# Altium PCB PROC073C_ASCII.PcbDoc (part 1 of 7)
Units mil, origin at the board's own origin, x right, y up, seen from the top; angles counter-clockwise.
Board outline 2165.35 x 2695.12 mil, 8 copper layers (Top Layer, L2_GND, L3_SIGNAL 1, L4_SIGNAL 2, L5_SIGNAL 3, L6_SIGNAL 4, L7_GND, Bottom Layer), stack 55.9 mil thick; 393 components, 319 nets, 1311 pads, 1643 vias.
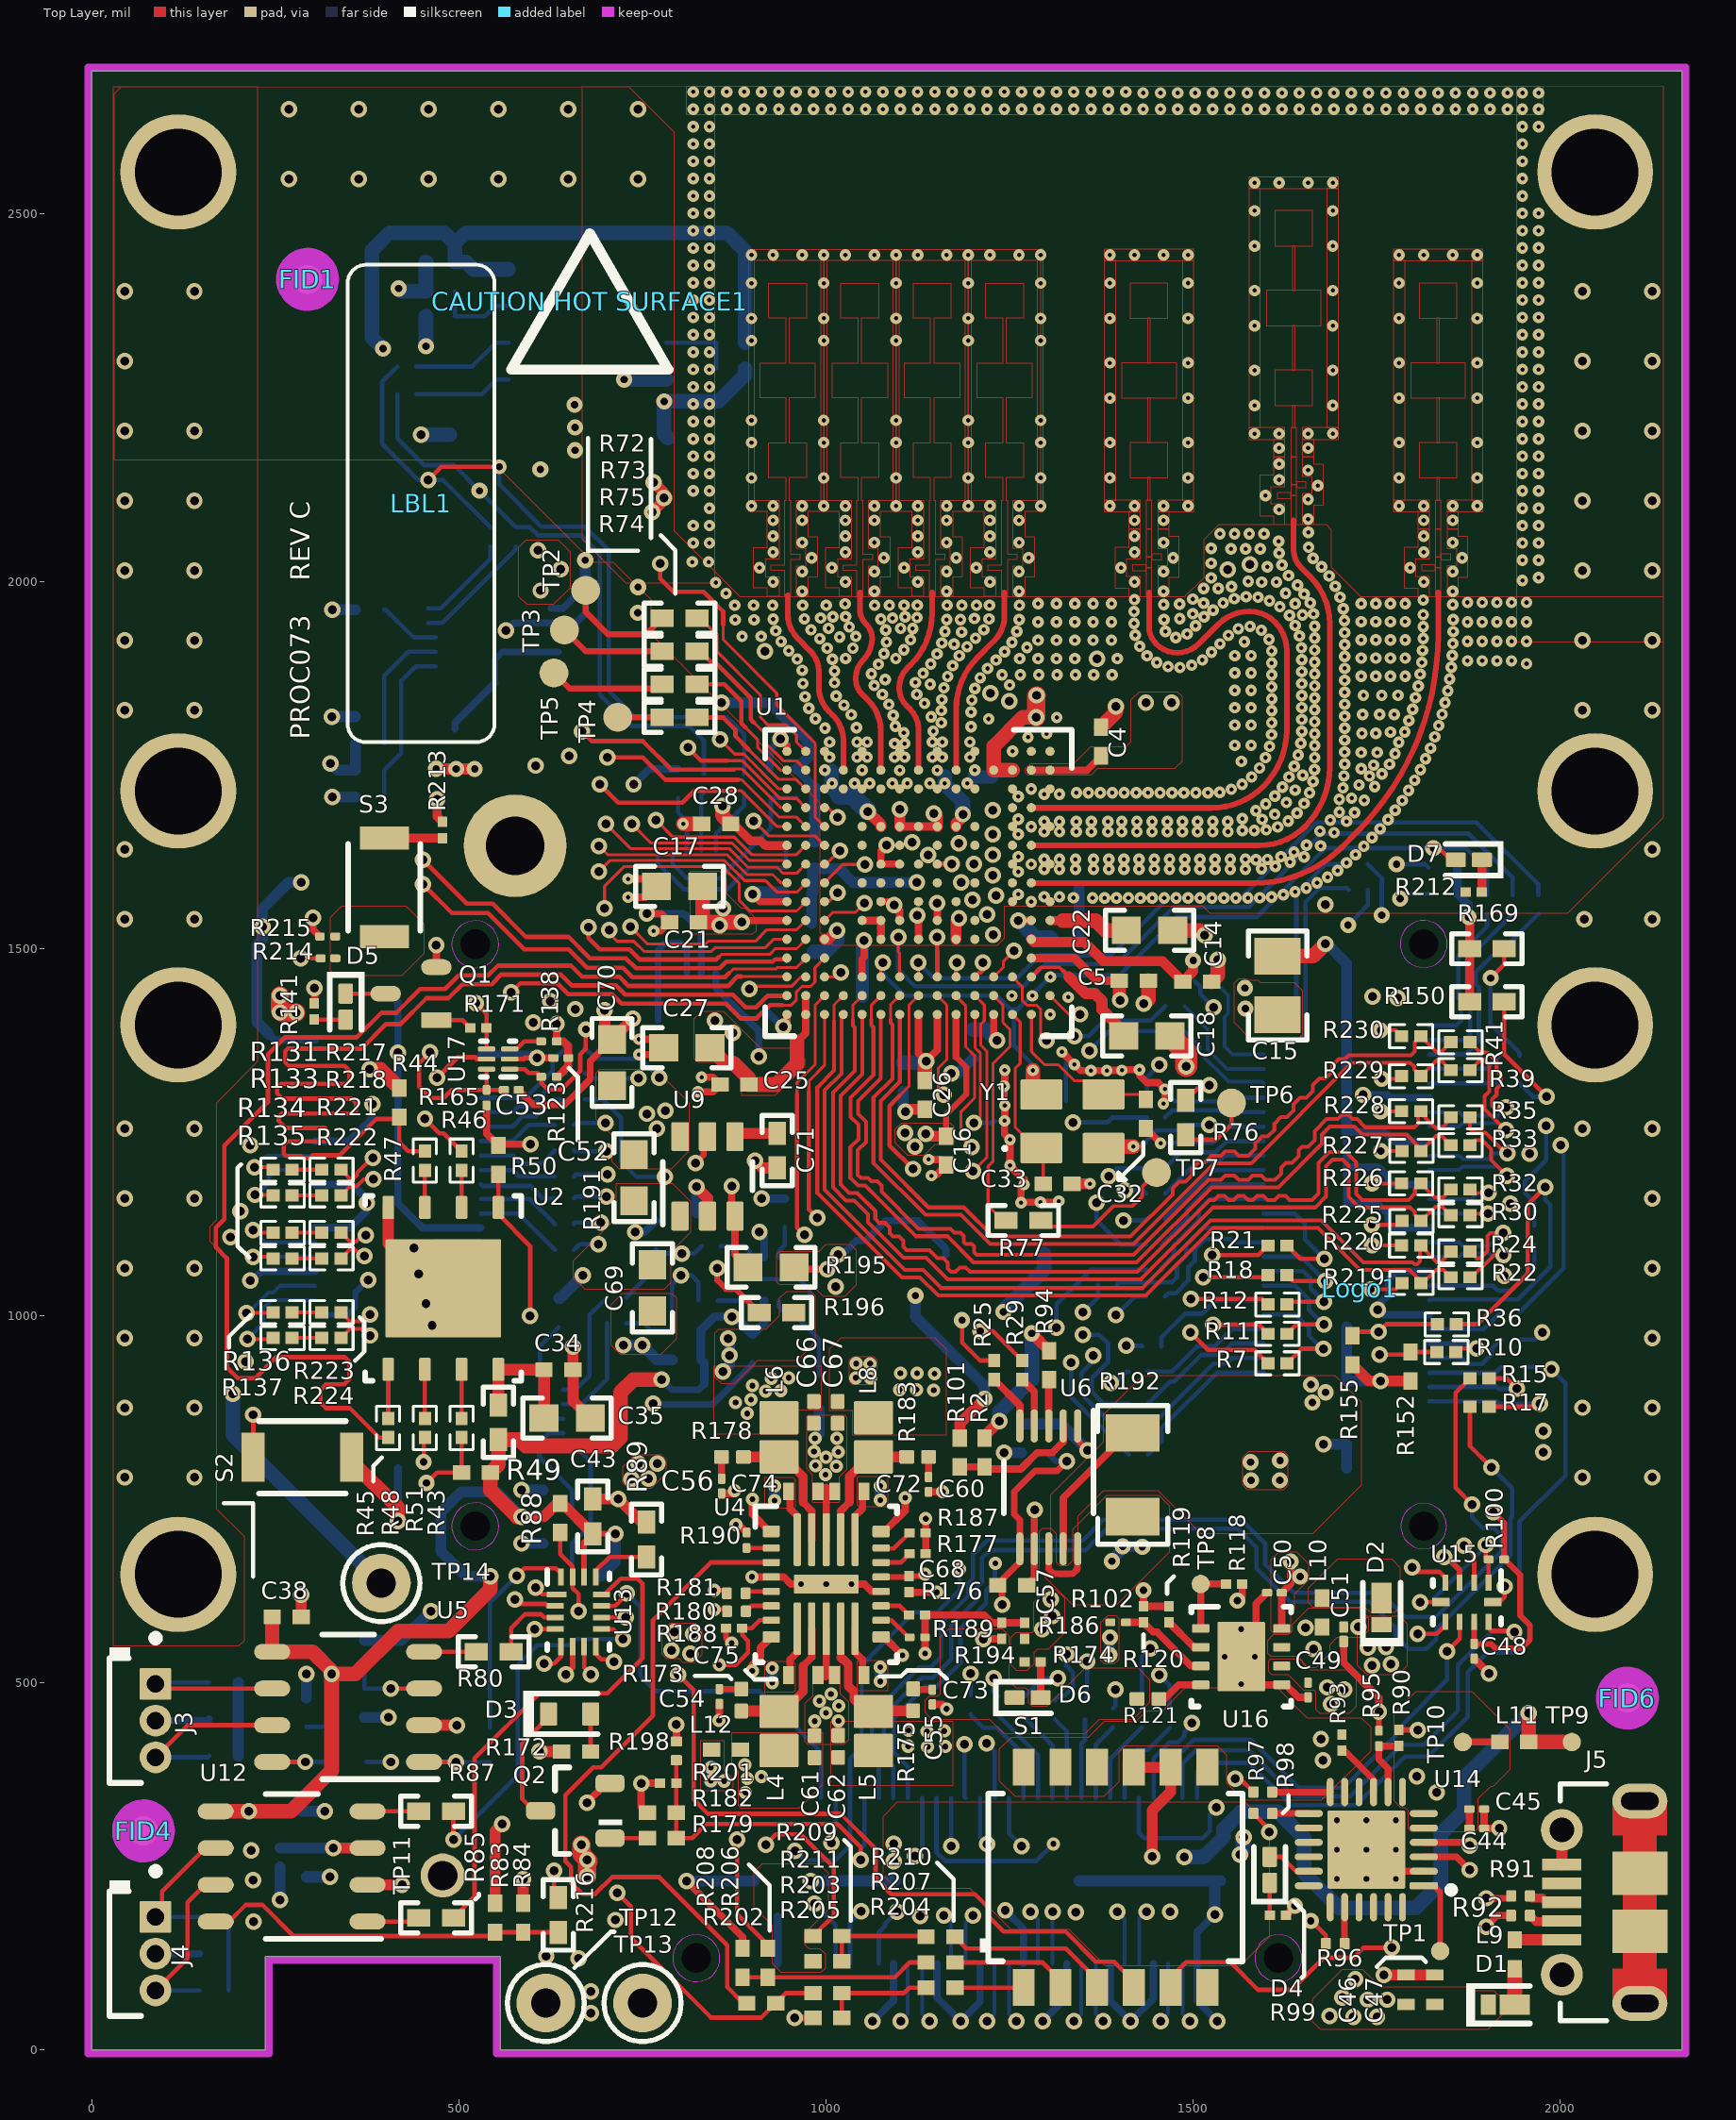
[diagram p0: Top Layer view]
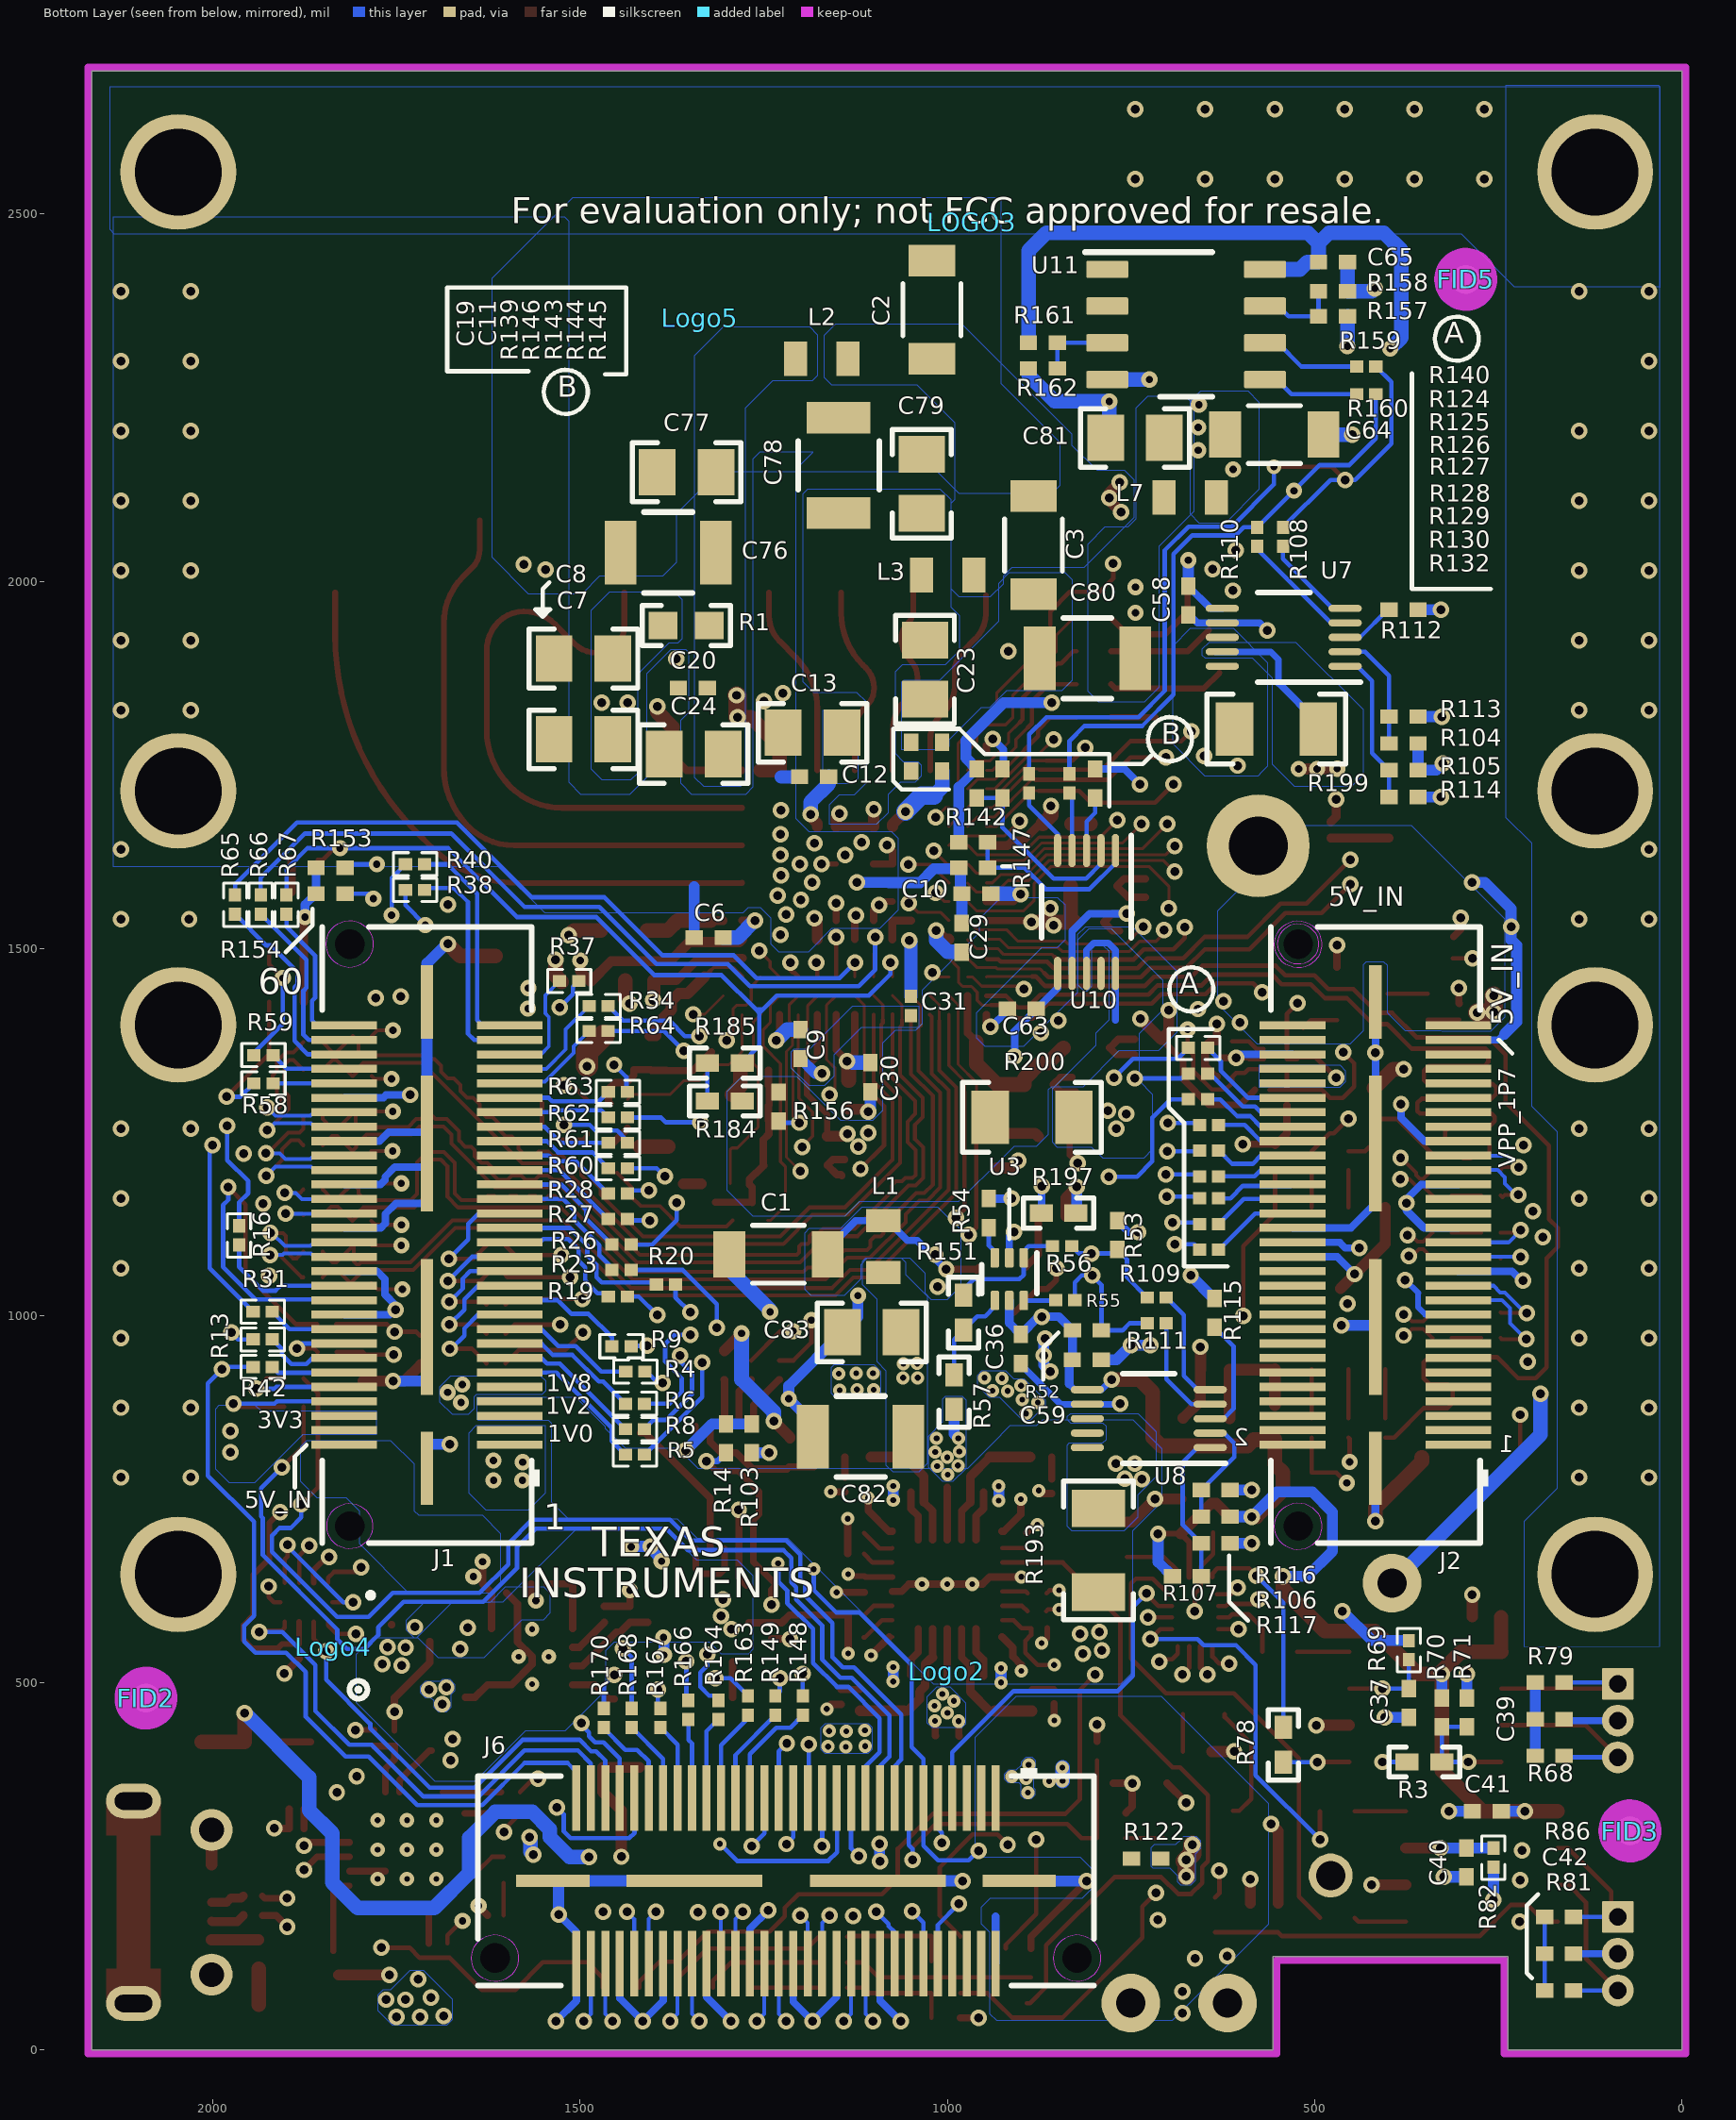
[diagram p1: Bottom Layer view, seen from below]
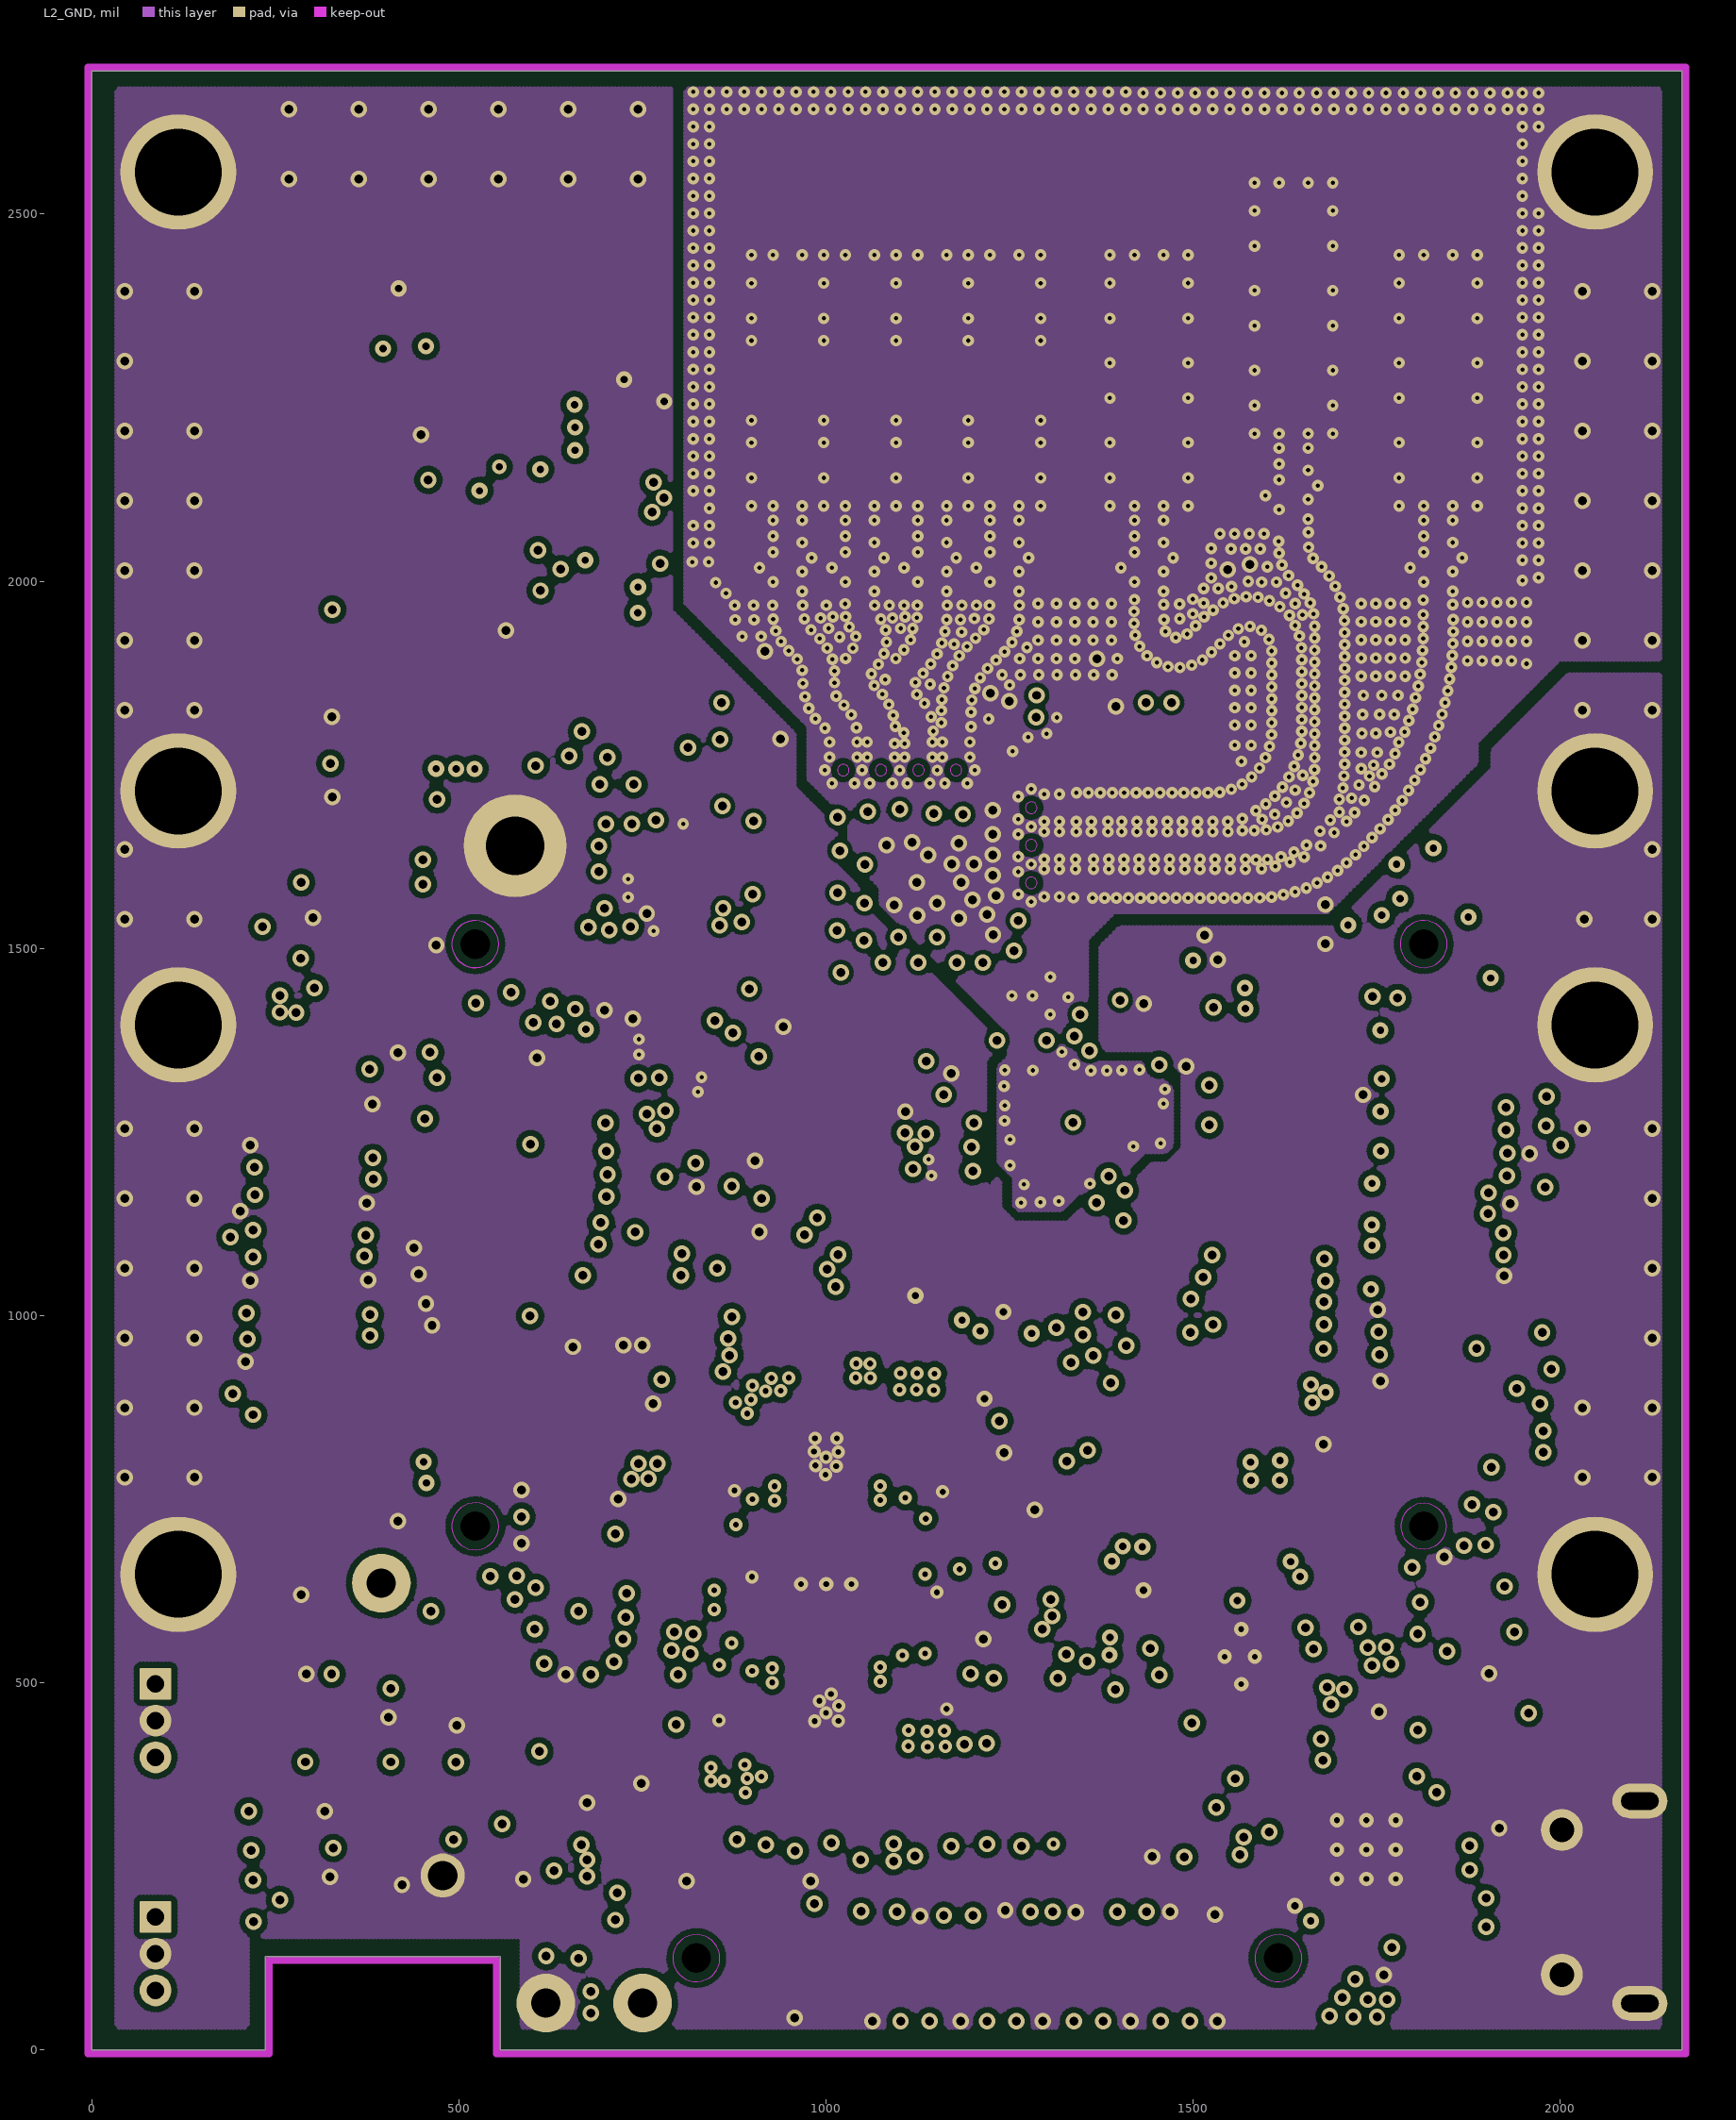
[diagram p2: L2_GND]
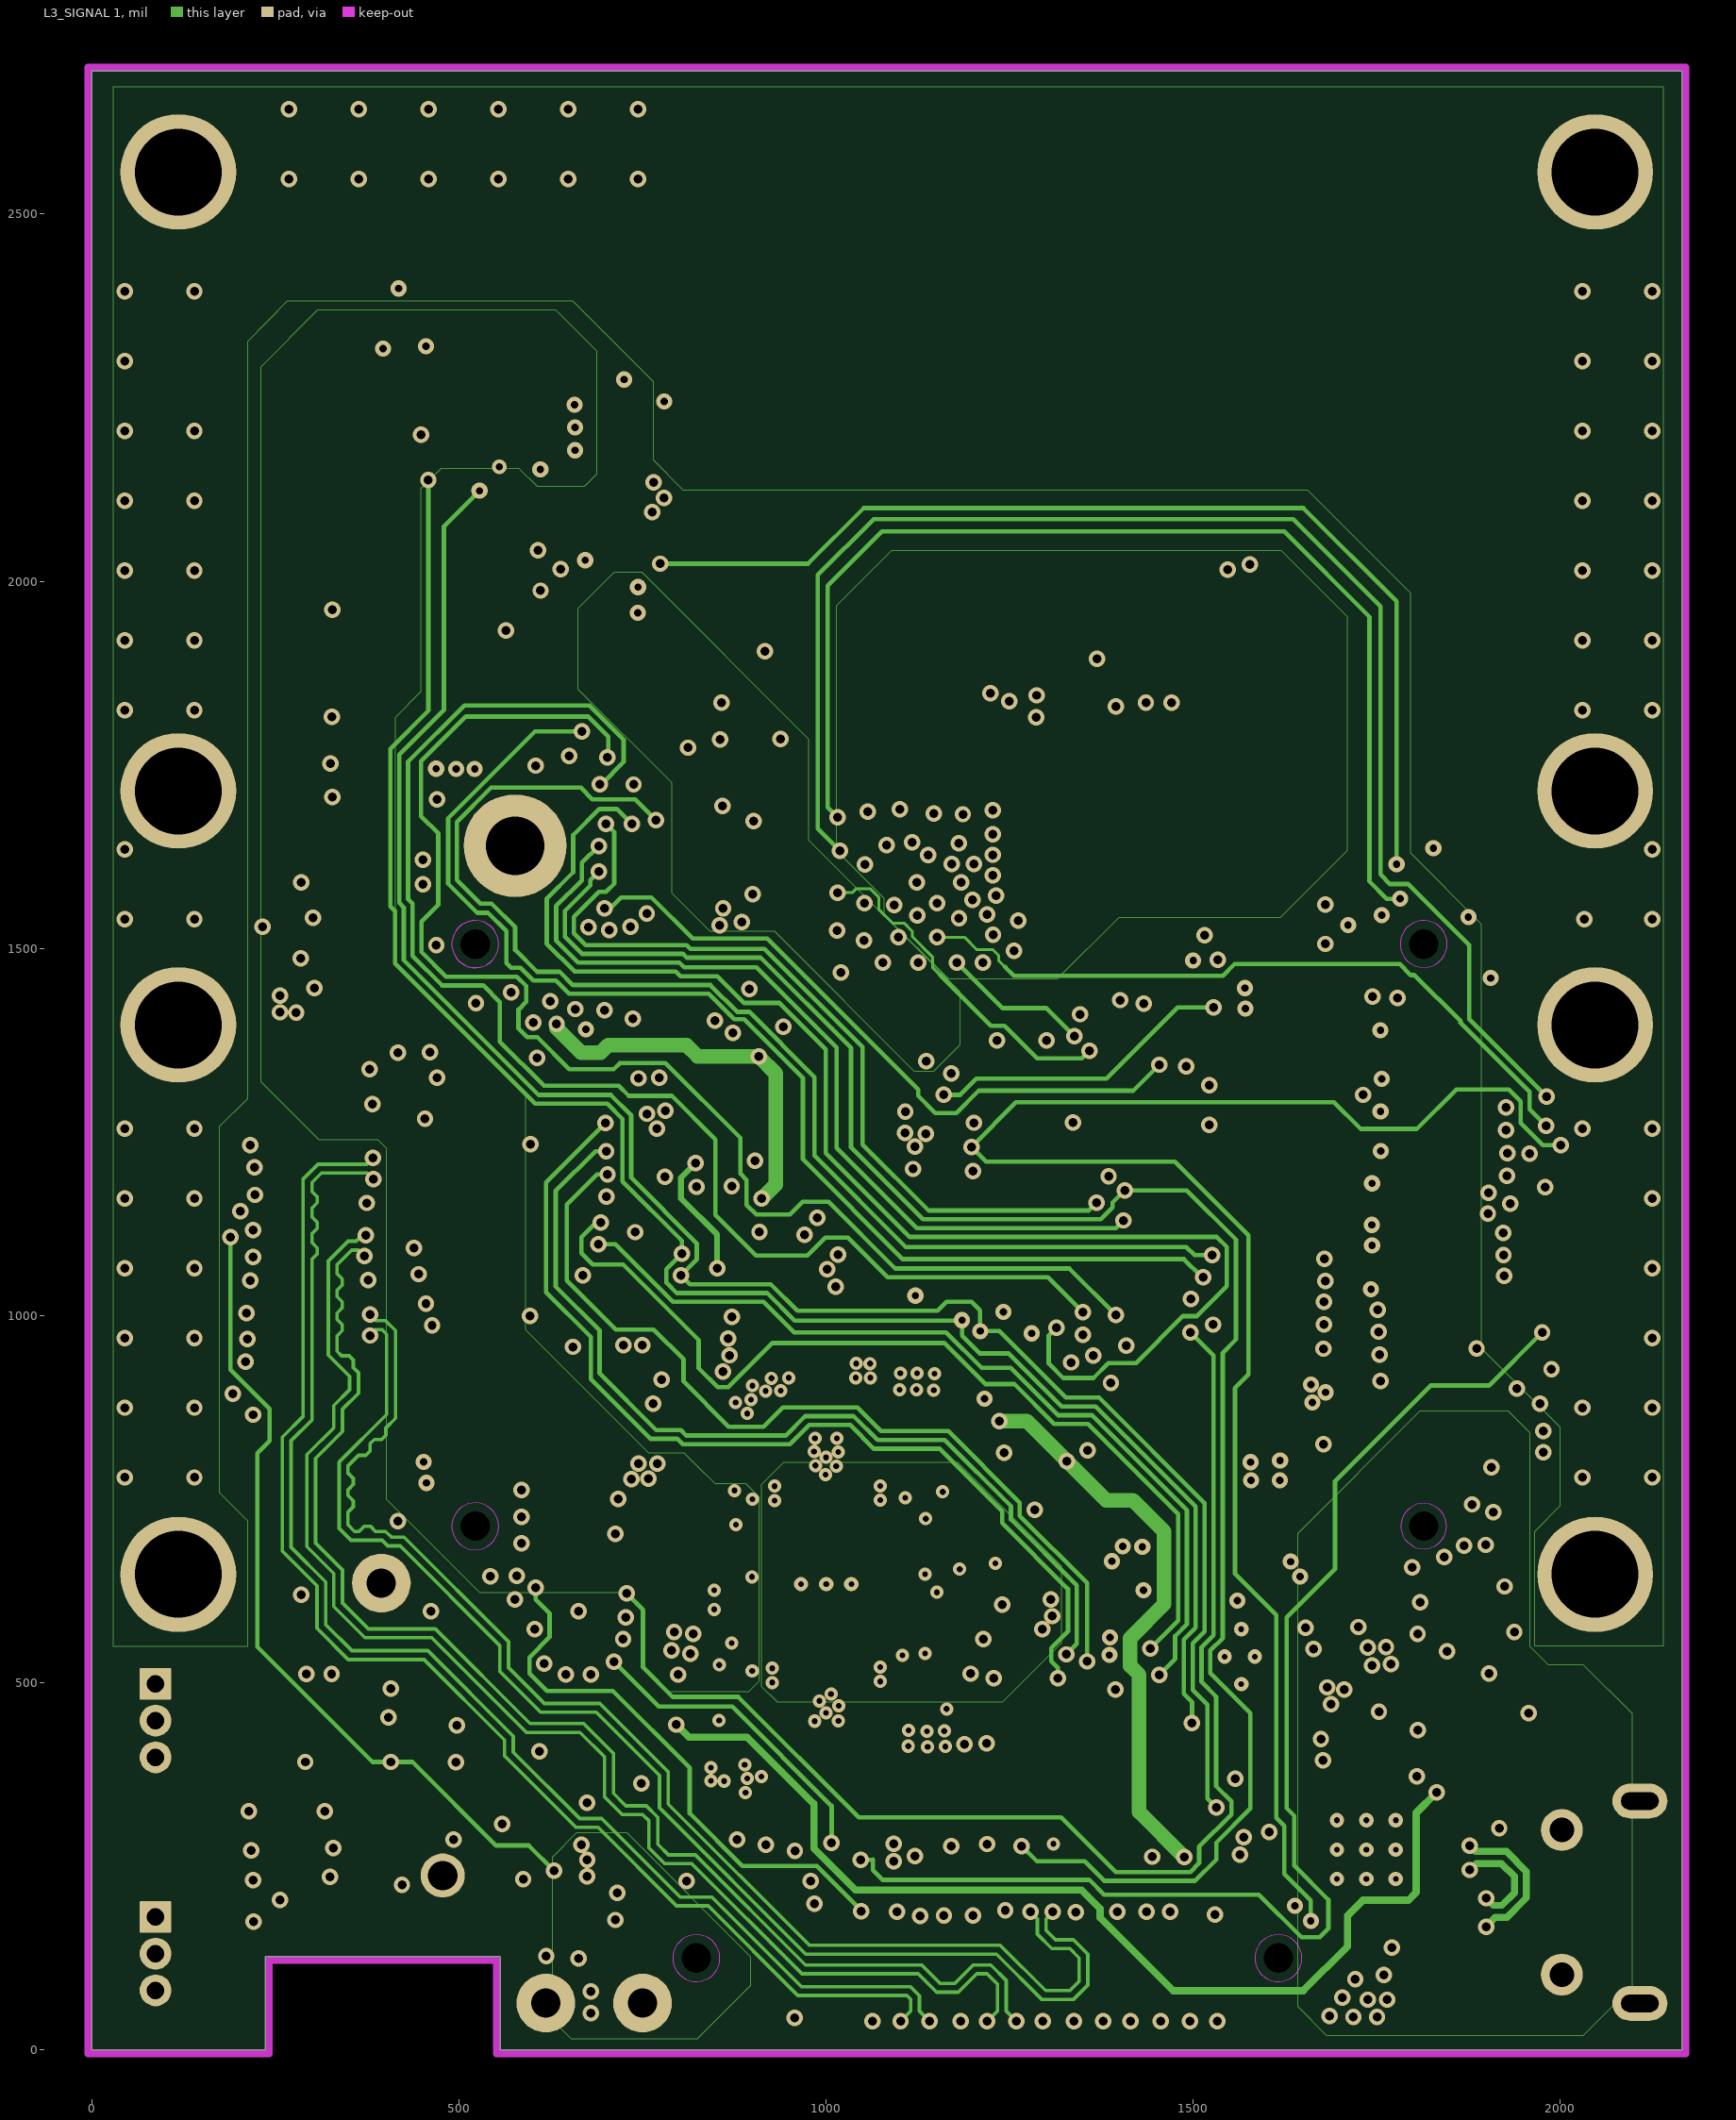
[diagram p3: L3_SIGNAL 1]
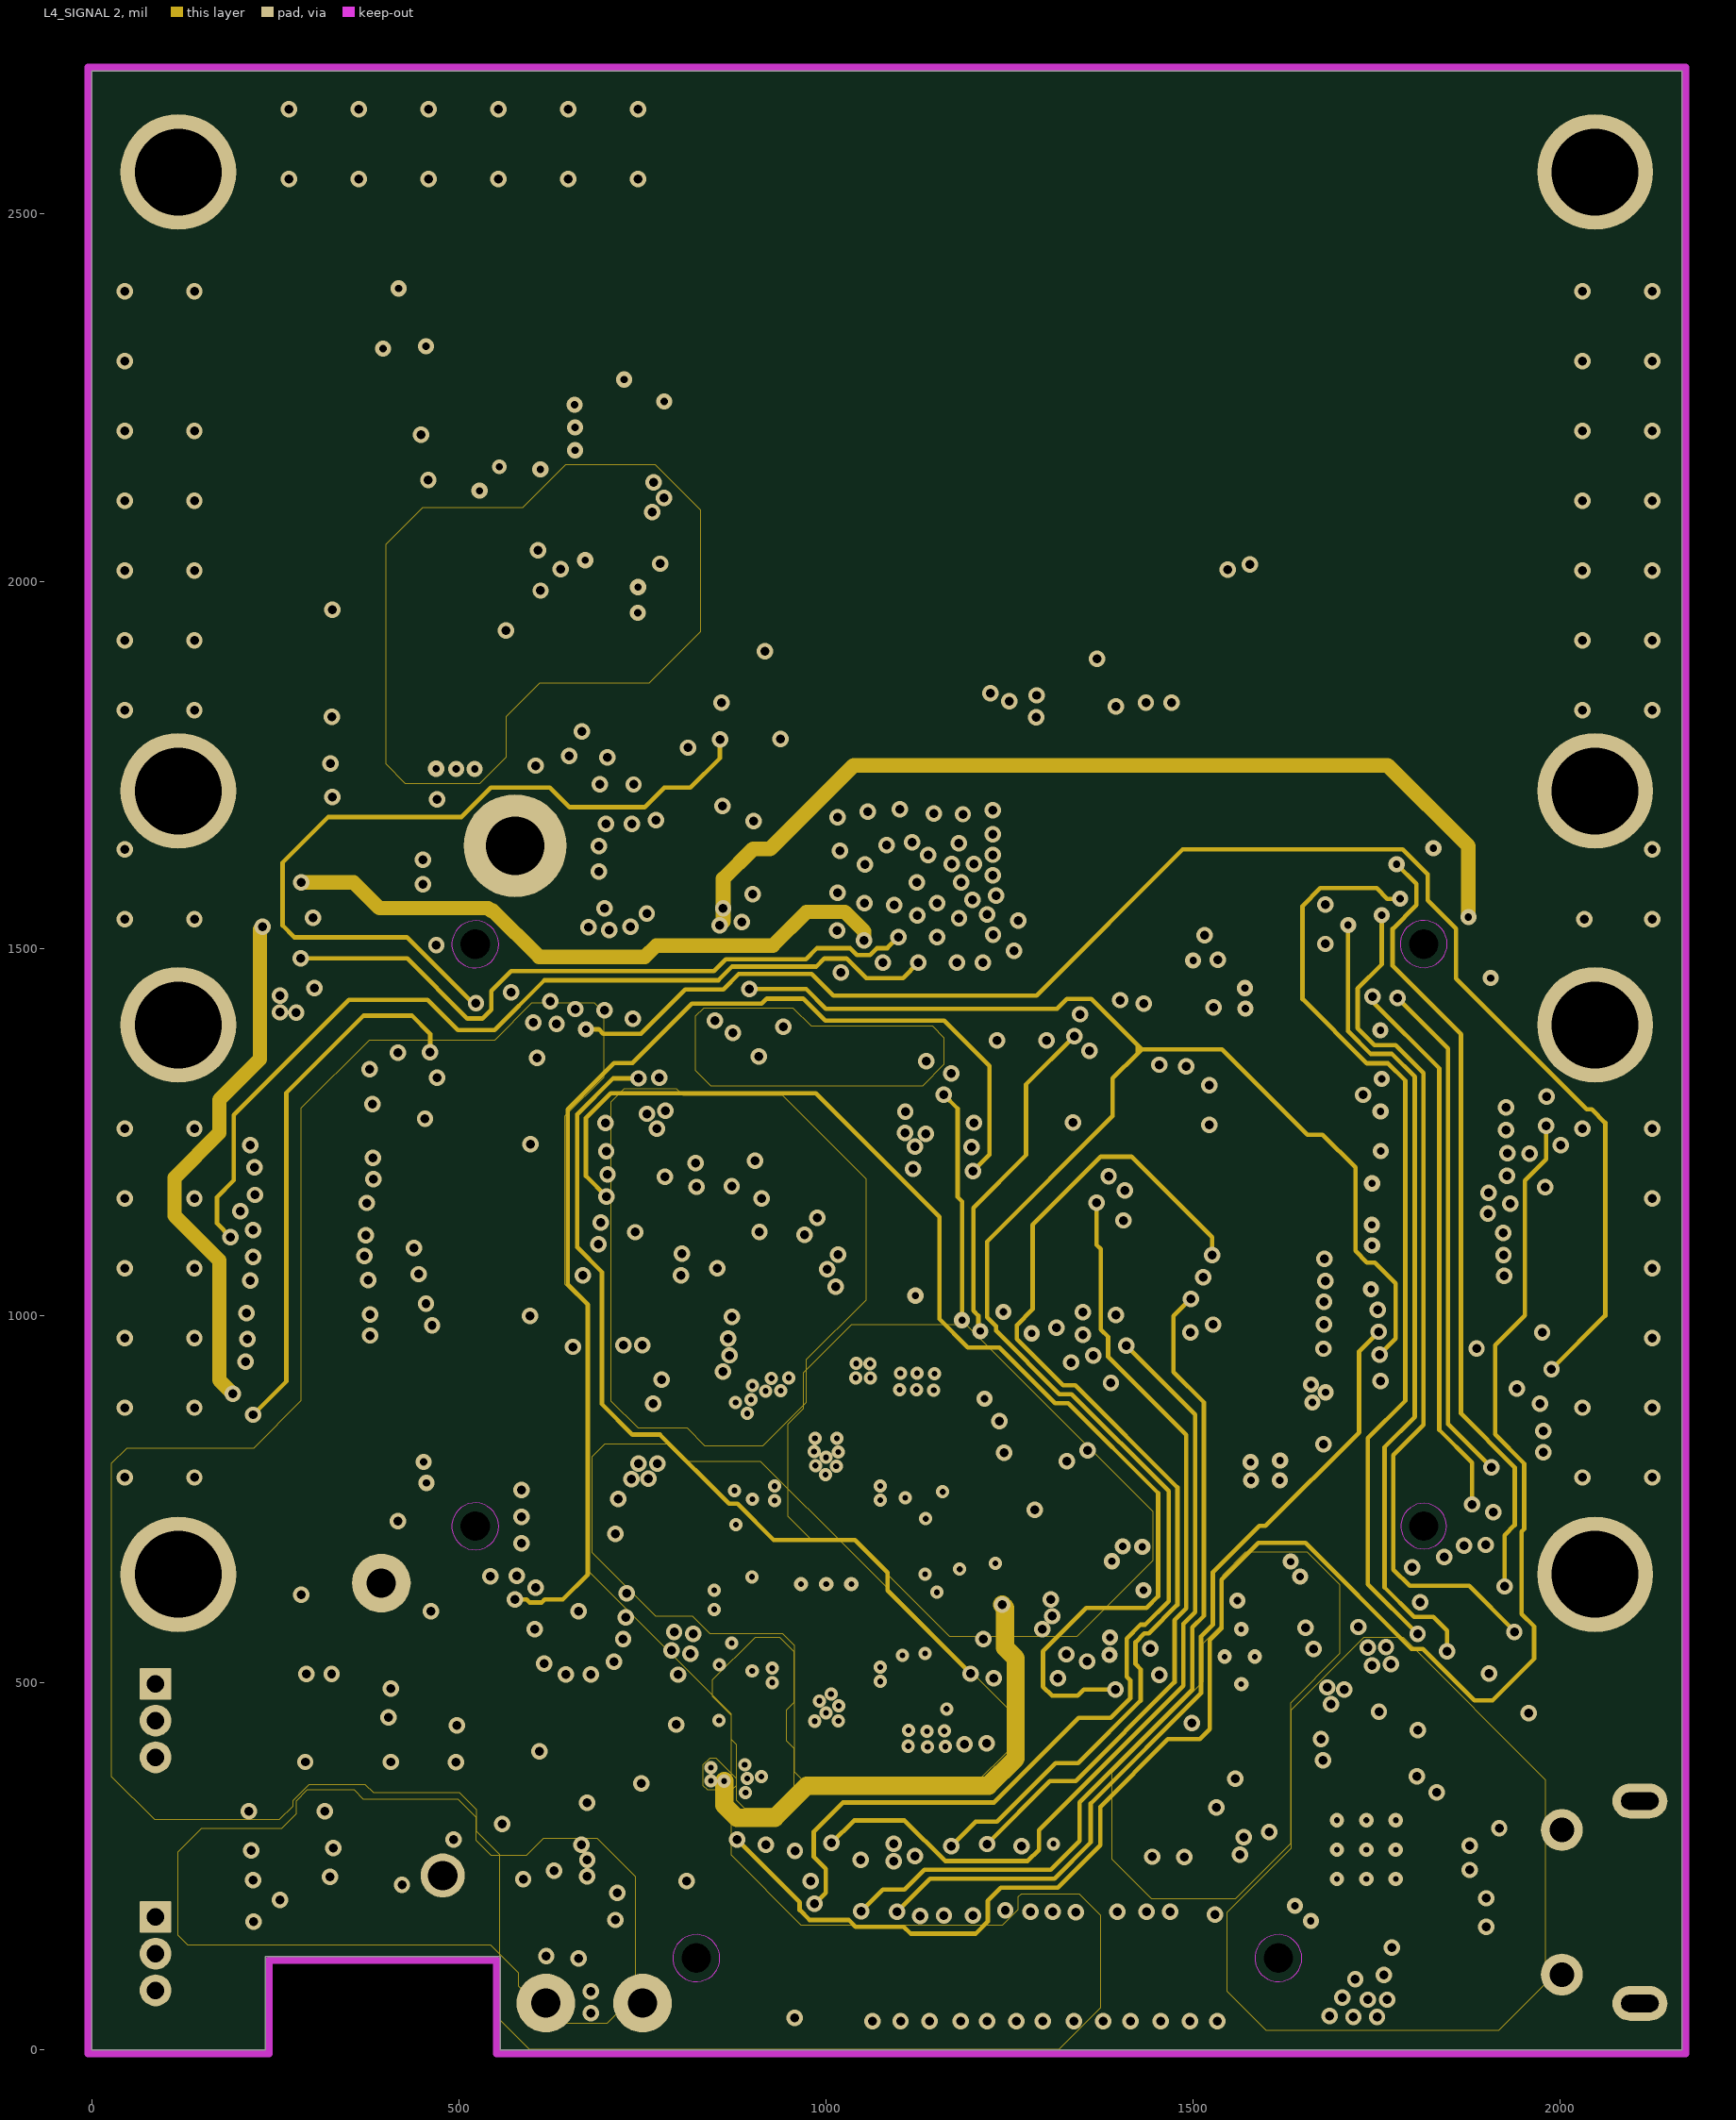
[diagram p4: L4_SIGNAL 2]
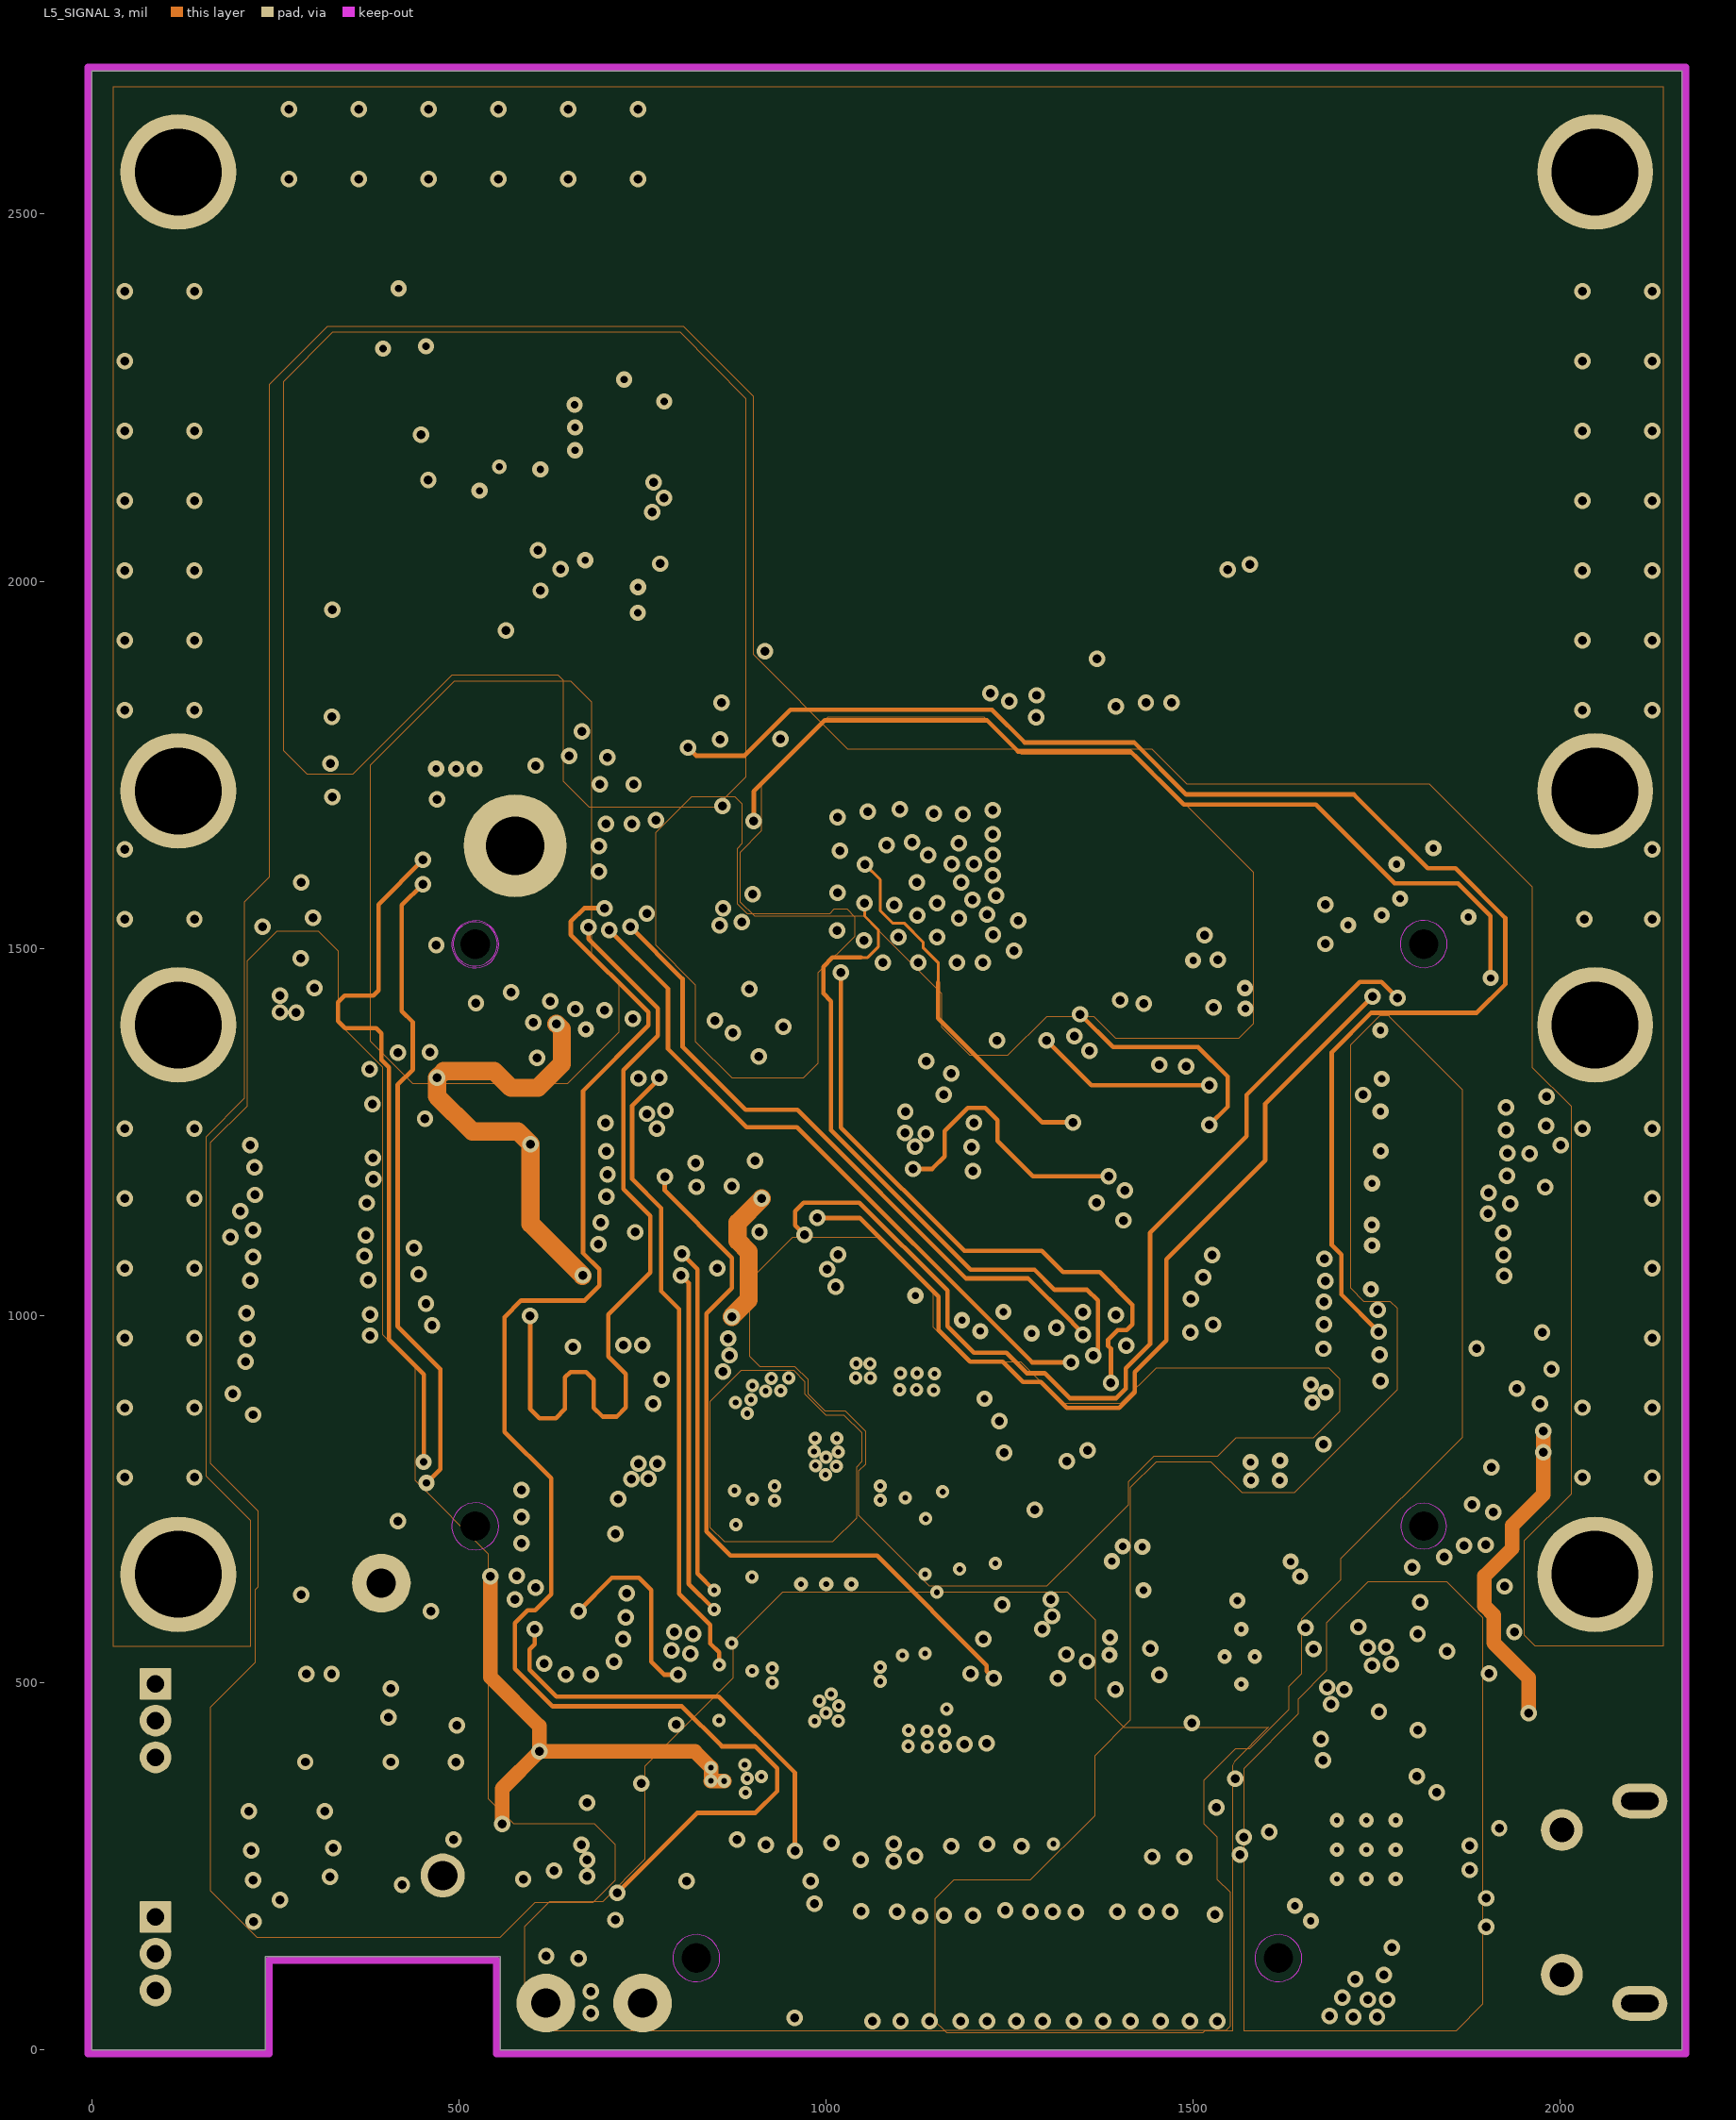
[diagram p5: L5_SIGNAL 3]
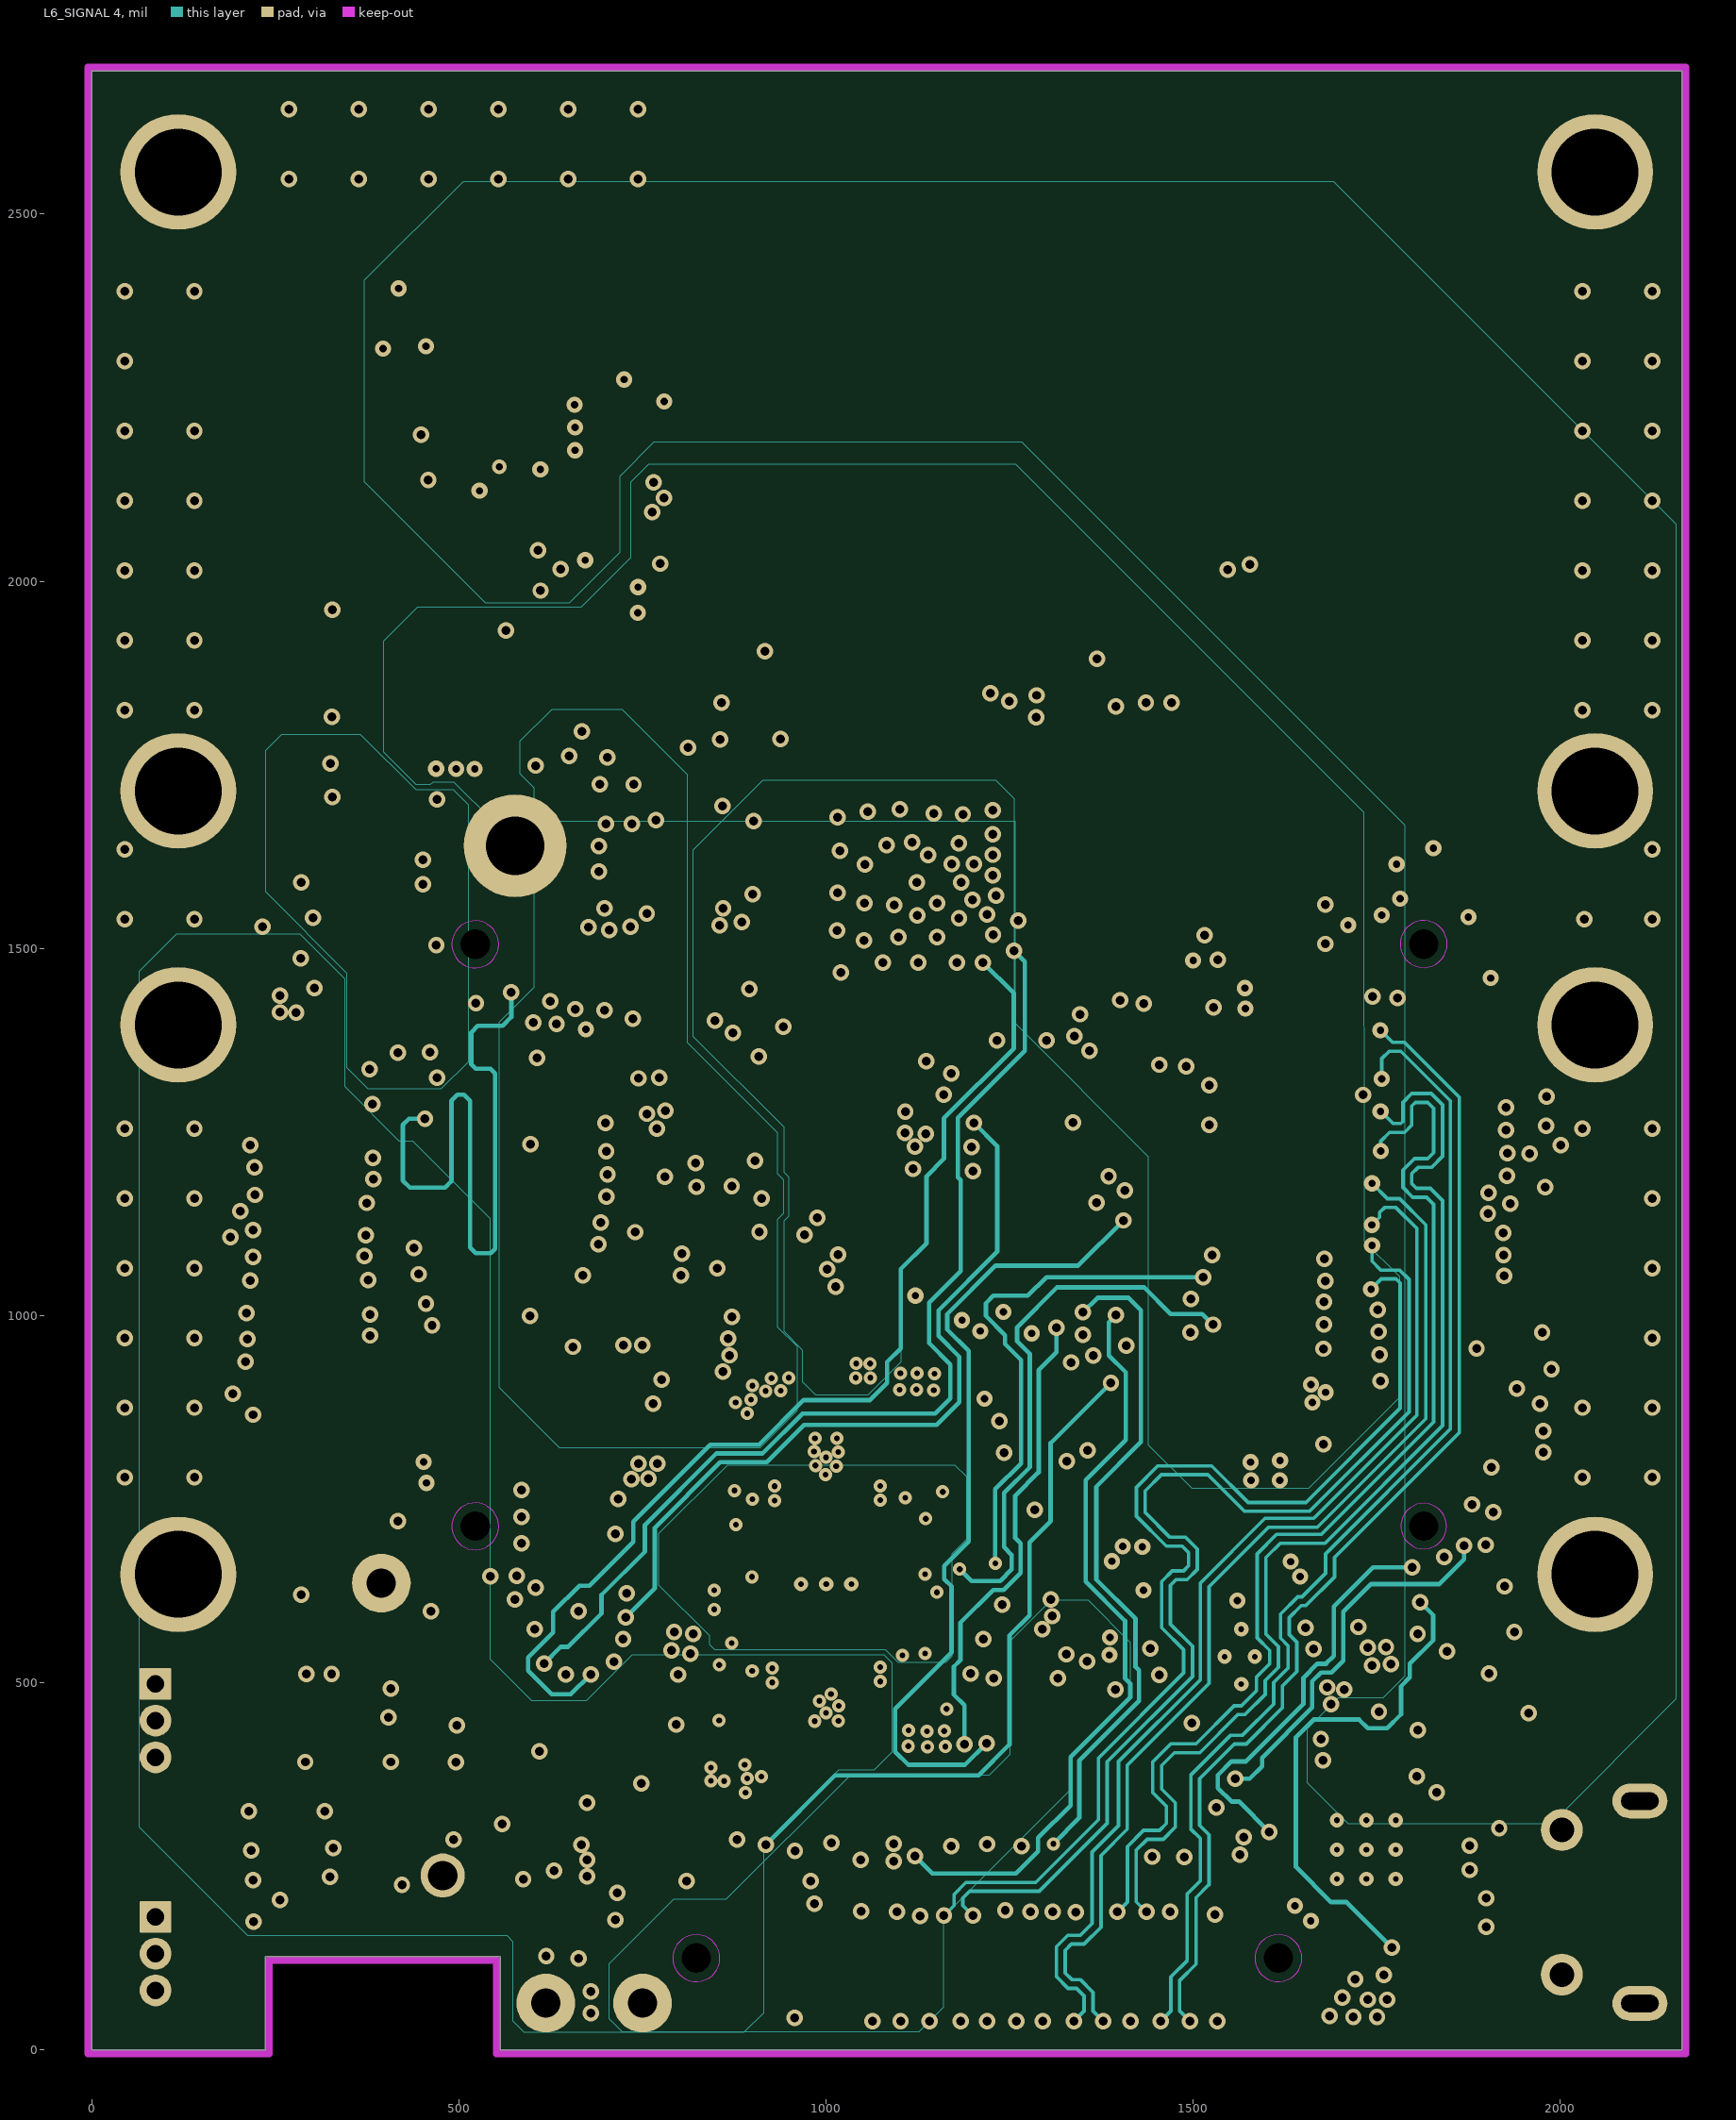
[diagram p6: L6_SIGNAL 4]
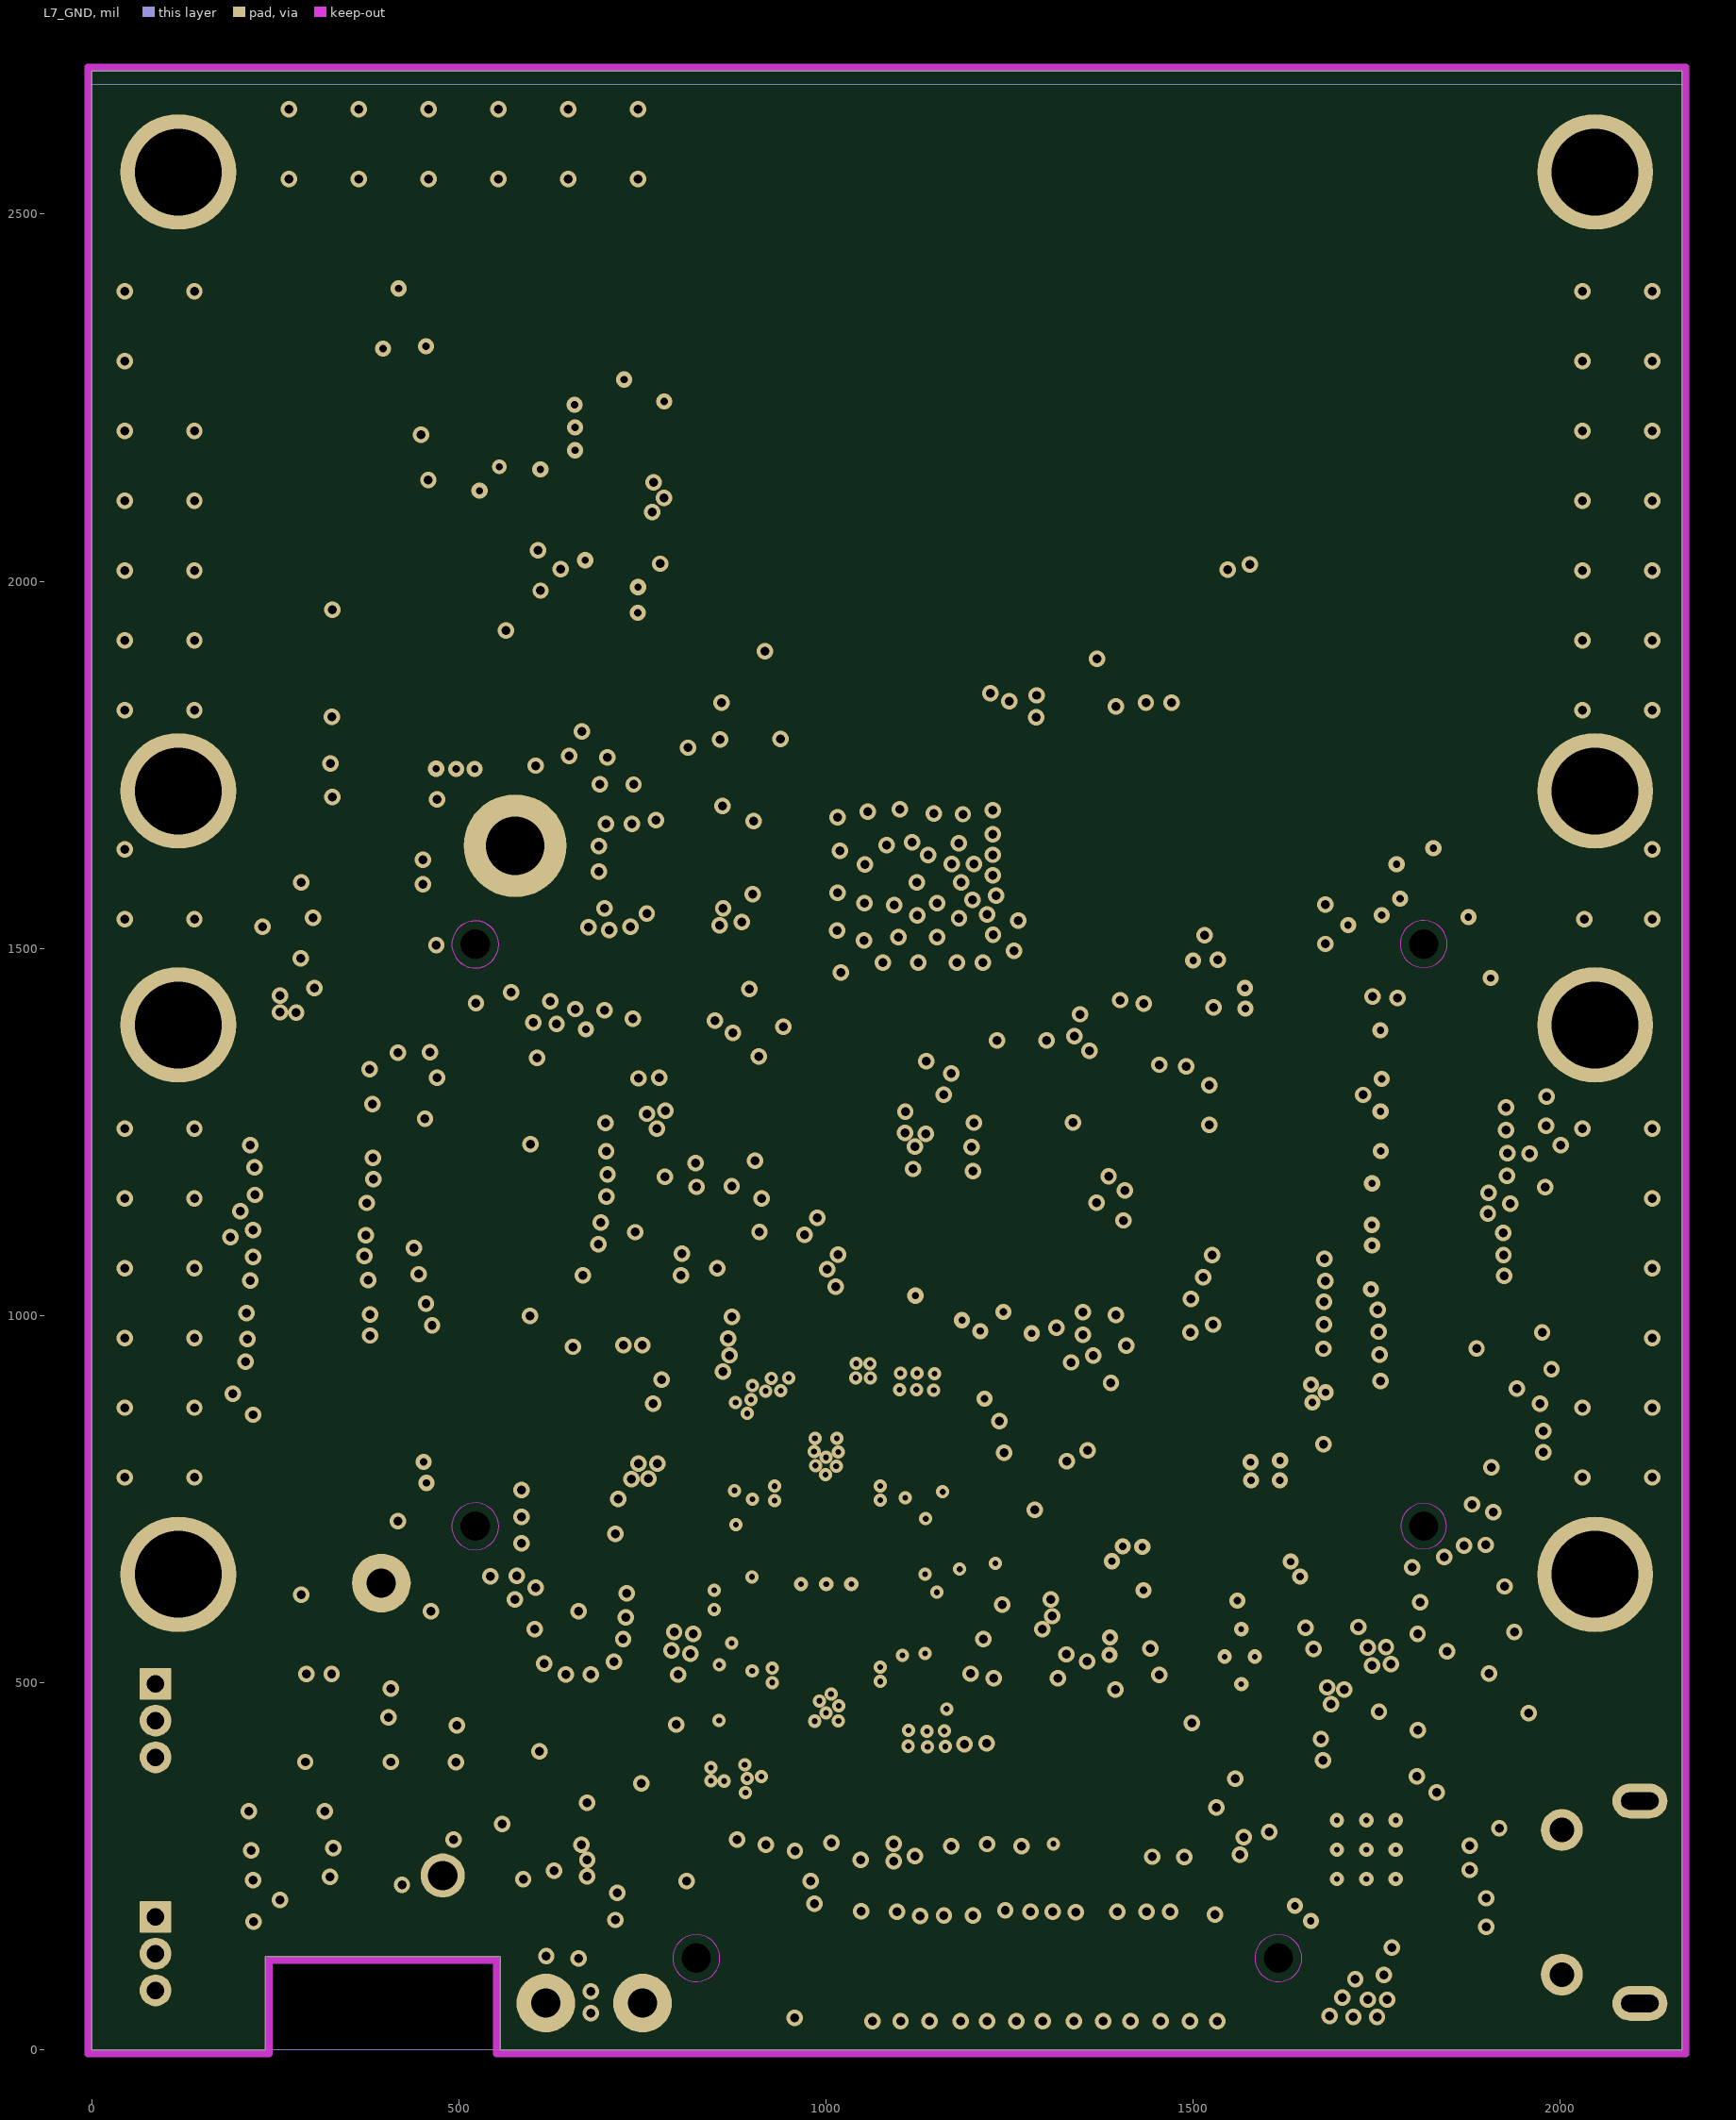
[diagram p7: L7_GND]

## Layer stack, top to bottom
Top Solder: solder mask 0.8, Solder Resist, Dk 1
Top Layer: signal copper 1.6
Dielectric 1: core 3.9, RO4835 LOPRO, Dk 3.5
L2_GND: signal copper 1.4
Dielectric 2: prepreg 5.5, PCL370HR, Dk 4.17
L3_SIGNAL 1: signal copper 1.4
Dielectric 3: core 10, PCL370HR, Dk 4.17
L4_SIGNAL 2: signal copper 1.4
Dielectric 4: prepreg 5.5, PCL370HR, Dk 4.17
L5_SIGNAL 3: signal copper 1.4
Dielectric 5: prepreg 10, PCL370HR, Dk 4.17
L6_SIGNAL 4: signal copper 1.4
Dielectric 6: core 5.5, PCL370HR, Dk 4.17
L7_GND: signal copper 1.4
Dielectric 7: core 3.9, PCL370HR, Dk 4.17
Bottom Layer: signal copper 1.6
Bottom Solder: solder mask 0.8, Solder Resist, Dk 1

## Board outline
0,0 0,2695.12 2165.35,2695.12 2165.35,0 556.54,0 556.54,127.3 236.54,127.3 236.54,0

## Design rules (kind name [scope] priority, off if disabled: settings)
AcuteAngle [All] p0 off: scope1count=1 scope1_0_kind=Board scope1_0_value=Board scope2count=1 scope2_0_kind=Board scope2_0_value=Board commentlength=0 minimum=4.50000000000000E+0001
AcuteAngle [All] p1 off: minimum=4.50000000000000E+0001 checktracksonly=FALSE
AssemblyTestPointUsage [All] p0: scope1count=1 scope1_0_kind=Board scope1_0_value=Board scope2count=1 scope2_0_kind=Board scope2_0_value=Board commentlength=0
AssemblyTestPointUsage [All] p1: valid=2
AssemblyTestpoint [All] p0: scope1count=1 scope1_0_kind=Board scope1_0_value=Board scope2count=1 scope2_0_kind=Board scope2_0_value=Board commentlength=0
Clearance Clearance_KO-J5 [All] p0 off: scope1count=1 scope1_0_kind=Board scope1_0_value=Board scope2count=1 scope2_0_kind=Component scope2_0_value=J5 commentlength=60 gap=19.6 // Protel DXP Scope 1 Expression Was: IsKeepOut and IsTrack
Clearance Clearance_Keepout [All] p0 off: scope1count=1 scope1_0_kind=Board scope1_0_value=Board scope2count=1 scope2_0_kind=Board scope2_0_value=Board commentlength=60 gap=20 // Protel DXP Scope 1 Expression Was: IsKeepOut and IsTrack
Clearance Clearance_LVDS_Track [All] p0 off: scope1count=1 scope1_0_kind=Board scope1_0_value=Board scope2count=1 scope2_0_kind=Board scope2_0_value=Board commentlength=69 gap=5 // Protel DXP Scope 2 Expression Was: istrack and InNetClass('LVDS')
Clearance Clearance_LVDS [All] p0 off: scope1count=1 scope1_0_kind=Board scope1_0_value=Board scope2count=1 scope2_0_kind=Board scope2_0_value=Board commentlength=108 gap=8 // Protel DXP Scope 2 Expression Was: (isvia or IsThruPin) and (not InNetClass('LVDS') or not InNet('GND'))
Clearance Clearance_Region [All] p0 off: scope1count=1 scope1_0_kind=Board scope1_0_value=Board scope2count=1 scope2_0_kind=Board scope2_0_value=Board commentlength=46 gap=5 // Protel DXP Scope 2 Expression Was: IsTrack
Clearance "Clr_L2_GND Cut out (400 Mircrons)" [All] p0 off: scope1count=1 scope1_0_kind=Board scope1_0_value=Board scope2count=1 scope2_0_kind=Board scope2_0_value=Board commentlength=48 gap=0 // Protel DXP Scope 2 Expression Was: IsKeepOut
Clearance "Clr_L1_GND Cut Out (800 Mirons)_1" [All] p0: scope1count=1 scope1_0_kind=Layer scope1_0_value=TOP scope2count=1 scope2_0_kind=Board scope2_0_value=Board commentlength=0 gap=6
Clearance "Clearance_Diff Pairs_LVDS" [All] p0: scope1count=1 scope1_0_kind=NetClass scope1_0_value="Diff Pairs" scope2count=1 scope2_0_kind=NetClass scope2_0_value="Diff Pairs" commentlength=0 gap=6
Clearance "Clr_L1_GND Cut Out (800 Mirons)" [All] p0 off: scope1count=1 scope1_0_kind=Board scope1_0_value=Board scope2count=1 scope2_0_kind=Board scope2_0_value=Board commentlength=48 gap=0 // Protel DXP Scope 2 Expression Was: IsKeepOut
Clearance "Clearance_TX and RX" [All] p0: scope1count=1 scope1_0_kind=NetClass scope1_0_value="TX and RX" scope2count=1 scope2_0_kind=Board scope2_0_value=Board commentlength=0 gap=8
Clearance Clearance_BGA [All] p0 off: scope1count=1 scope1_0_kind=Board scope1_0_value=Board scope2count=1 scope2_0_kind=Board scope2_0_value=Board commentlength=57 gap=4 // Protel DXP Scope 1 Expression Was: WithinRoom('BGA1')
Clearance [All] p0: scope1count=1 scope1_0_kind=Board scope1_0_value=Board scope2count=1 scope2_0_kind=Board scope2_0_value=Board commentlength=0 gap=8
Clearance Clearance_Fid [All] p0 off: scope1count=1 scope1_0_kind=Board scope1_0_value=Board scope2count=1 scope2_0_kind=Board scope2_0_value=Board commentlength=81 gap=0 // Protel DXP Scope 2 Expression Was: IsPad and InComponentClass('FiducialMark')
Clearance Clearance_KO-J5 [IsKeepOut and IsTrack vs InComponent('J5')] p1: gap=19.6 ignorepadtopadclearanceinfootprint=TRUE
Clearance Clearance_Keepout [IsKeepOut and IsTrack] p2: gap=20 ignorepadtopadclearanceinfootprint=TRUE
Clearance Clearance_LVDS_Track [istrack and InNetClass('LVDS') vs istrack and InNetClass('LVDS')] p3: gap=5 ignorepadtopadclearanceinfootprint=FALSE
Clearance Clearance_LVDS [InNetClass('LVDS') and IsTrack vs (isvia or IsThruPin) and (not InNetClass('LVDS') or not InNet('GND'))] p4: gap=8 ignorepadtopadclearanceinfootprint=FALSE
Clearance Clearance_Region [isregion and incomponent('U4') vs IsTrack] p5: gap=5 ignorepadtopadclearanceinfootprint=FALSE
Clearance "Clr_L2_GND Cut out (400 Mircrons)" [OnLayer('L2') and InPolygon vs IsKeepOut] p6: gap=0 ignorepadtopadclearanceinfootprint=FALSE except(7: Arc-Arc Arc-Track)
Clearance "Clr_L1_GND Cut Out (800 Mirons)_1" [OnLayer('L2')] p7: gap=6 ignorepadtopadclearanceinfootprint=FALSE except(0: Arc-Hole Track-Hole SMDPad-Hole THPad-Hole Via-Hole Fill-Hole Poly-Hole Region-Hole Text-Hole; 8: Arc-Fill Arc-Poly Arc-Region Track-Fill Track-Poly Track-Region SMDPad-Fill SMDPad-Poly SMDPad-Region THPad-Fill THPad-Poly THPad-Region Via-Fill Via-Poly Via-Region Fill-Fill Fill-Poly Fill-Region Poly-Poly Poly-Region Region-Region)
Clearance Clearance_Fid [IsKeepOut and InComponentClass('FiducialMark') vs IsPad and InComponentClass('FiducialMark')] p8: gap=0 ignorepadtopadclearanceinfootprint=FALSE
Clearance "Clearance_Diff Pairs_LVDS" [InNetClass('Diff Pairs') vs InNetClass('Diff Pairs')] p9: gap=6 ignorepadtopadclearanceinfootprint=FALSE except(0: Arc-Hole Track-Hole SMDPad-Hole THPad-Hole Via-Hole Fill-Hole Poly-Hole Region-Hole Text-Hole; 4: Arc-SMDPad Arc-THPad Arc-Via Track-SMDPad Track-THPad Track-Via; 5: Arc-Arc Arc-Track Track-Track; 8: Arc-Fill Arc-Poly Arc-Region Track-Fill Track-Poly Track-Region Via-Fill Via-Poly Via-Region Fill-Fill Fill-Poly Fill-Region Poly-Poly Poly-Region Region-Region)
Clearance "Clr_L1_GND Cut Out (800 Mirons)" [OnTopLayer and InPoly vs IsKeepOut] p10: gap=0 ignorepadtopadclearanceinfootprint=FALSE
Clearance "Clearance_TX and RX" [InNetClass('TX and RX')] p11: gap=8 ignorepadtopadclearanceinfootprint=FALSE except(0: Arc-Hole Track-Hole SMDPad-Hole THPad-Hole Via-Hole Fill-Hole Poly-Hole Region-Hole Text-Hole; 4: Arc-Text Track-Text SMDPad-Text THPad-Text Via-Text Fill-Text Poly-Text Region-Text Text-Text; 7.7: Fill-Fill Fill-Poly Fill-Region Poly-Poly Poly-Region Region-Region; 7.9: Arc-Via Track-Via; 10: Arc-SMDPad Arc-THPad Track-SMDPad Track-THPad SMDPad-SMDPad SMDPad-THPad SMDPad-Via THPad-THPad THPad-Via)
Clearance Clearance_BGA [WithinRoom('BGA1')] p12: gap=4 ignorepadtopadclearanceinfootprint=FALSE except(0: Arc-Hole Track-Hole SMDPad-Hole THPad-Hole Via-Hole Fill-Hole Poly-Hole Region-Hole Text-Hole; 6: SMDPad-Poly THPad-Poly Via-Poly; 7.5: Region-Region; 7.87: Arc-Text Track-Text SMDPad-Text THPad-Text Via-Text Fill-Text Poly-Text Region-Text Text-Text; 8: Arc-Poly Track-THPad Track-Poly THPad-THPad Fill-Poly Poly-Poly)
Clearance [All] p13: gap=8 ignorepadtopadclearanceinfootprint=TRUE except(0: Arc-Hole Track-Hole SMDPad-Hole THPad-Hole Via-Hole Fill-Hole Poly-Hole Region-Hole Text-Hole; 4: Arc-SMDPad Track-SMDPad; 5.1: SMDPad-SMDPad; 6: Arc-Arc Arc-Track Arc-THPad Arc-Via Arc-Text Track-Track Track-THPad Track-Via Track-Text SMDPad-THPad SMDPad-Via SMDPad-Text THPad-THPad THPad-Via THPad-Text Via-Via Via-Text Fill-Text Poly-Text Region-Text Text-Text)
ComponentClearance ComponentClearance_MatingCon-3D [All] p0 off: scope1count=1 scope1_0_kind=Board scope1_0_value=Board scope2count=1 scope2_0_kind=Board scope2_0_value=Board commentlength=57 gap=0 collisioncheckmode=3 // Protel DXP Scope 2 Expression Was: not InAnyComponent
ComponentClearance "ComponentClearance_WEE Logo" [All] p0: scope1count=1 scope1_0_kind=Component scope1_0_value=Logo4 scope2count=1 scope2_0_kind=Board scope2_0_value=Board commentlength=0 gap=0 collisioncheckmode=3
ComponentClearance ComponentClearance_R77 [All] p0: scope1count=1 scope1_0_kind=Component scope1_0_value=R77 scope2count=1 scope2_0_kind=Component scope2_0_value=Logo1 commentlength=0 gap=0 collisioncheckmode=3
ComponentClearance ComponentClearance_Logo [All] p0: scope1count=1 scope1_0_kind=ComponentClass scope1_0_value=Logo scope2count=1 scope2_0_kind=Board scope2_0_value=Board commentlength=0 gap=0 collisioncheckmode=3
ComponentClearance "ComponentClearance_Mounting Holes_Fiducial Marks" [All] p0: scope1count=1 scope1_0_kind=ComponentClass scope1_0_value=FiducialMark scope2count=1 scope2_0_kind=PadClass scope2_0_value="Mounting Holes PADS" commentlength=0 gap=50 collisioncheckmode=3
ComponentClearance [All] p0: scope1count=1 scope1_0_kind=Board scope1_0_value=Board scope2count=1 scope2_0_kind=Board scope2_0_value=Board commentlength=0 gap=10 collisioncheckmode=3
ComponentClearance ComponentClearance_MatingCon-3D [All vs not InAnyComponent] p1: gap=0 collisioncheckmode=3 verticalgap=0 showdistances=FALSE
ComponentClearance "ComponentClearance_WEE Logo" [InComponent('Logo4')] p2: gap=0 collisioncheckmode=3 verticalgap=0 showdistances=TRUE
ComponentClearance ComponentClearance_R77 [InComponent('R77') vs InComponent('Logo1')] p3: gap=0 collisioncheckmode=3 verticalgap=0 showdistances=TRUE
ComponentClearance ComponentClearance_Logo [InComponentClass('Logo')] p4: gap=0 collisioncheckmode=3 verticalgap=0 showdistances=TRUE
ComponentClearance "ComponentClearance_Mounting Holes_Fiducial Marks" [InComponentClass('FiducialMark') vs InPadClass('Mounting Holes PADS')] p5: gap=50 collisioncheckmode=3 verticalgap=10 showdistances=TRUE
ComponentClearance [All] p6: gap=10 collisioncheckmode=3 verticalgap=10 showdistances=TRUE
DiffPairsRouting DiffPairsRouting_BGA [All] p0 off: scope1count=1 scope1_0_kind=Board scope1_0_value=Board scope2count=1 scope2_0_kind=Board scope2_0_value=Board commentlength=57 // Protel DXP Scope 1 Expression Was: WithinRoom('BGA1')
DiffPairsRouting [All] p0: scope1count=1 scope1_0_kind=Board scope1_0_value=Board scope2count=1 scope2_0_kind=Board scope2_0_value=Board commentlength=0
DiffPairsRouting DiffPairsRouting_BGA [WithinRoom('BGA1')] p1: maxlimit=10 minlimit=10 mostfreqgap=10 toplayer_minwidth=4 toplayer_maxwidth=5.2 toplayer_prefwidth=4 midlayer1_minwidth=4 midlayer1_maxwidth=5.2 midlayer1_prefwidth=4 midlayer2_minwidth=4 midlayer2_maxwidth=5.2 midlayer2_prefwidth=4 midlayer3_minwidth=4 midlayer3_maxwidth=5.2 midlayer3_prefwidth=4 midlayer4_minwidth=4 midlayer4_maxwidth=5.2 midlayer4_prefwidth=4 midlayer5_minwidth=4 midlayer5_maxwidth=5.2 midlayer5_prefwidth=4 midlayer6_minwidth=4 midlayer6_maxwidth=5.2 midlayer6_prefwidth=4 bottomlayer_minwidth=4 bottomlayer_maxwidth=5.2 bottomlayer_prefwidth=4 maxuncoupledlength=500
DiffPairsRouting [All] p2: maxlimit=7.2 minlimit=5 mostfreqgap=7.2 toplayer_maxgap=5 toplayer_prefgap=5 toplayer_minwidth=4 toplayer_maxwidth=5.2 toplayer_prefwidth=5.2 midlayer1_mingap=7.2 midlayer1_minwidth=4.8 midlayer1_maxwidth=4.8 midlayer1_prefwidth=4.8 midlayer2_mingap=7.2 midlayer2_minwidth=4.8 midlayer2_maxwidth=4.8 midlayer2_prefwidth=4.8 midlayer3_mingap=7.2 midlayer3_minwidth=4.8 midlayer3_maxwidth=4.8 midlayer3_prefwidth=4.8 midlayer4_mingap=7.2 midlayer4_minwidth=4.8 midlayer4_maxwidth=4.8 midlayer4_prefwidth=4.8 midlayer5_mingap=7.2 midlayer5_minwidth=4.8 midlayer5_maxwidth=4.8 midlayer5_prefwidth=4.8 midlayer6_mingap=7.2 midlayer6_minwidth=4.8 midlayer6_maxwidth=4.8 midlayer6_prefwidth=4.8 bottomlayer_maxgap=5 bottomlayer_prefgap=5 bottomlayer_minwidth=5.2 bottomlayer_maxwidth=5.2 bottomlayer_prefwidth=5.2 maxuncoupledlength=500
FabricationTestPointUsage TestPointUsage [All] p0: scope1count=1 scope1_0_kind=Board scope1_0_value=Board scope2count=1 scope2_0_kind=Board scope2_0_value=Board commentlength=0 valid=2 allowmultiple=FALSE
FabricationTestPointUsage TestPointUsage [All] p1: valid=2 allowmultiple=FALSE
FabricationTestpoint Testpoint [All] p0: scope1count=1 scope1_0_kind=Board scope1_0_value=Board scope2count=1 scope2_0_kind=Board scope2_0_value=Board commentlength=0 side=3 testpointundercomponent=TRUE minsize=40 maxsize=100 preferedsize=60 minholesize=0 maxholesize=40 preferedholesize=32 testpointgrid=1
FabricationTestpoint Testpoint [All] p1: side=3 testpointundercomponent=TRUE minsize=40 maxsize=100 preferedsize=60 minholesize=0 maxholesize=40 preferedholesize=32 testpointgrid=1 allowsidetop=TRUE allowsidebottom=TRUE usegrid=TRUE gridtolerance=0.01
FanoutControl Fanout_LCC [All] p0 off: scope1count=1 scope1_0_kind=Board scope1_0_value=Board scope2count=1 scope2_0_kind=Board scope2_0_value=Board commentlength=69 // Protel DXP Scope 1 Expression Was: IsLCC   Fanout_LCC (Default Rule)
FanoutControl Fanout_BGA [All] p0 off: scope1count=1 scope1_0_kind=Board scope1_0_value=Board scope2count=1 scope2_0_kind=Board scope2_0_value=Board commentlength=69 // Protel DXP Scope 1 Expression Was: IsBGA   Fanout_BGA (Default Rule)
FanoutControl Fanout_SOIC [All] p0 off: scope1count=1 scope1_0_kind=Board scope1_0_value=Board scope2count=1 scope2_0_kind=Board scope2_0_value=Board commentlength=71 // Protel DXP Scope 1 Expression Was: IsSOIC   Fanout_SOIC (Default Rule)
FanoutControl Fanout_Default [All] p0: scope1count=1 scope1_0_kind=Board scope1_0_value=Board scope2count=1 scope2_0_kind=Board scope2_0_value=Board commentlength=30 // Fanout_Default (Default Rule)
FanoutControl Fanout_Small [All] p0 off: scope1count=1 scope1_0_kind=Board scope1_0_value=Board scope2count=1 scope2_0_kind=Board scope2_0_value=Board commentlength=84 // Protel DXP Scope 1 Expression Was: (CompPinCount < 5)   Fanout_Small (Default Rule)
FanoutControl Fanout_LCC [IsLCC] p1: bgadir=Out bgaviamode=Centered fanoutstyle=Auto fanoutdirection=Alternating viagrid=1 // Fanout_LCC (Default Rule)
FanoutControl Fanout_BGA [IsBGA] p2: bgadir=Out bgaviamode=Centered fanoutstyle=Auto fanoutdirection=Alternating viagrid=1 // Fanout_BGA (Default Rule)
FanoutControl Fanout_Default [All] p4: bgadir=Out bgaviamode=Centered fanoutstyle=Auto fanoutdirection=Alternating viagrid=1 // Fanout_Default (Default Rule)
FanoutControl Fanout_Small [(CompPinCount < 5)] p5: bgadir=Out bgaviamode=Centered fanoutstyle=Auto fanoutdirection=OutThenIn viagrid=1 // Fanout_Small (Default Rule)
Height Room_Hieght [All] p0 off: scope1count=1 scope1_0_kind=Board scope1_0_value=Board scope2count=1 scope2_0_kind=Board scope2_0_value=Board commentlength=69 // Protel DXP Scope 1 Expression Was: WithinRoom('Room_Hieght 1 MM')
Height Room_Hieght [WithinRoom('Room_Hieght 1 MM')] p1: minheight=0 maxheight=41.34 prefheight=39.37
HoleSize [All] p0: scope1count=1 scope1_0_kind=Board scope1_0_value=Board scope2count=1 scope2_0_kind=Board scope2_0_value=Board commentlength=0 absolutevalues=TRUE maxlimit=280 minlimit=5.9 maxpercent=80.000 minpercent=20.000
HoleSize [All] p1: absolutevalues=TRUE maxlimit=280 minlimit=5.9 maxpercent=80.000 minpercent=20.000
HoleToHoleClearance HoleToHoleClearance_1 [All] p0 off: scope1count=1 scope1_0_kind=Board scope1_0_value=Board scope2count=1 scope2_0_kind=Board scope2_0_value=Board commentlength=77 // Protel DXP Scope 2 Expression Was: InDrillLayerPair('Top Layer - L2_GND')
HoleToHoleClearance [All] p0: scope1count=1 scope1_0_kind=Board scope1_0_value=Board scope2count=1 scope2_0_kind=Board scope2_0_value=Board commentlength=0
HoleToHoleClearance HoleToHoleClearance_1 [InDrillLayerPair('Top Layer - L2_GND') vs InDrillLayerPair('Top Layer - L2_GND')] p1: gap=7.7 allowstackedmicrovias=TRUE
HoleToHoleClearance [All] p2: gap=8 allowstackedmicrovias=TRUE
LayerPairs [All] p0: scope1count=1 scope1_0_kind=Board scope1_0_value=Board scope2count=1 scope2_0_kind=Board scope2_0_value=Board commentlength=0 enforce=TRUE
MatchedLengths MatchedLengths_SPI [All] p0 off: scope1count=1 scope1_0_kind=Board scope1_0_value=Board scope2count=1 scope2_0_kind=Board scope2_0_value=Board commentlength=60 tolerance=2 amplitude=200 gap=20 style=90-Degree // Protel DXP Scope 1 Expression Was: InxSignalClass('SPI')
MatchedLengths MatchedLengths-J2-J6 [All] p0 off: scope1count=1 scope1_0_kind=Board scope1_0_value=Board scope2count=1 scope2_0_kind=Board scope2_0_value=Board commentlength=62 tolerance=15 amplitude=200 gap=20 style=90-Degree // Protel DXP Scope 1 Expression Was: InxSignalClass('J2-J6')
MatchedLengths MatchedLengths_U1-J6 [All] p0 off: scope1count=1 scope1_0_kind=Board scope1_0_value=Board scope2count=1 scope2_0_kind=Board scope2_0_value=Board commentlength=62 tolerance=15 amplitude=200 gap=20 style=90-Degree // Protel DXP Scope 1 Expression Was: InxSignalClass('U1-J6')
MatchedLengths MatchedLengths-U1-J1 [All] p0 off: scope1count=1 scope1_0_kind=Board scope1_0_value=Board scope2count=1 scope2_0_kind=Board scope2_0_value=Board commentlength=62 tolerance=15 amplitude=200 gap=20 style=90-Degree // Protel DXP Scope 1 Expression Was: InxSignalClass('U1-J1')
MatchedLengths MatchedLengths_Pairs [All] p0 off: scope1count=1 scope1_0_kind=Board scope1_0_value=Board scope2count=1 scope2_0_kind=Board scope2_0_value=Board commentlength=69 tolerance=10 amplitude=200 gap=20 style=90-Degree // Protel DXP Scope 1 Expression Was: InxSignalClass('All xSignals')
MatchedLengths MatchedLengths_SPI [InxSignalClass('SPI')] p1: tolerance=2 checknetsindiffpair=FALSE checkdiffpairvsdiffpair=TRUE checkxsignals=TRUE checkothers=TRUE
MatchedLengths MatchedLengths-J2-J6 [InxSignalClass('J2-J6')] p2: tolerance=15 checknetsindiffpair=FALSE checkdiffpairvsdiffpair=TRUE checkxsignals=TRUE checkothers=TRUE
MatchedLengths MatchedLengths_U1-J6 [InxSignalClass('U1-J6')] p3: tolerance=15 checknetsindiffpair=FALSE checkdiffpairvsdiffpair=TRUE checkxsignals=TRUE checkothers=TRUE
MatchedLengths MatchedLengths-U1-J1 [InxSignalClass('U1-J1')] p4: tolerance=15 checknetsindiffpair=FALSE checkdiffpairvsdiffpair=TRUE checkxsignals=TRUE checkothers=TRUE
MatchedLengths MatchedLengths_Pairs [InxSignalClass('All xSignals')] p5: tolerance=10 checknetsindiffpair=TRUE checkdiffpairvsdiffpair=FALSE checkxsignals=FALSE checkothers=FALSE
MinimumAnnularRing MinimumAnnularRing_ThermalPadVias [All] p0 off: scope1count=1 scope1_0_kind=Board scope1_0_value=Board scope2count=1 scope2_0_kind=Board scope2_0_value=Board commentlength=63 minimumring=3.9 // Protel DXP Scope 1 Expression Was: IsVia and InAnyComponent
MinimumAnnularRing [All] p0: scope1count=1 scope1_0_kind=Board scope1_0_value=Board scope2count=1 scope2_0_kind=Board scope2_0_value=Board commentlength=0 minimumring=3.9
MinimumAnnularRing MinimumAnnularRing_ThermalPadVias [IsVia and InAnyComponent] p1: minimumring=3.9
MinimumAnnularRing [All] p2: minimumring=3.9
MinimumSolderMaskSliver MinimumSolderMaskSliver_Logo [All] p0: scope1count=1 scope1_0_kind=ComponentClass scope1_0_value=Logo scope2count=1 scope2_0_kind=ComponentClass scope2_0_value=Logo commentlength=0
MinimumSolderMaskSliver [All] p0: scope1count=1 scope1_0_kind=Board scope1_0_value=Board scope2count=1 scope2_0_kind=Board scope2_0_value=Board commentlength=0
MinimumSolderMaskSliver MinimumSolderMaskSliver_Logo [InComponentClass('Logo') vs InComponentClass('Logo')] p1: minsoldermaskwidth=0.7
MinimumSolderMaskSliver [All] p2: minsoldermaskwidth=3.5
NetAntennae [All] p0: scope1count=1 scope1_0_kind=Board scope1_0_value=Board scope2count=1 scope2_0_kind=Board scope2_0_value=Board commentlength=0
PasteMaskExpansion [All] p0: scope1count=1 scope1_0_kind=Board scope1_0_value=Board scope2count=1 scope2_0_kind=Board scope2_0_value=Board commentlength=0 expansion=0
PlaneClearance [All] p0: scope1count=1 scope1_0_kind=Board scope1_0_value=Board scope2count=1 scope2_0_kind=Board scope2_0_value=Board commentlength=0 clearance=20
PlaneConnect [All] p0: scope1count=1 scope1_0_kind=Board scope1_0_value=Board scope2count=1 scope2_0_kind=Board scope2_0_value=Board commentlength=0 planeconnectstyle=Relief reliefexpansion=10 reliefentries=4 reliefconductorwidth=10 reliefairgap=10
PlaneConnect [All] p1: planeconnectstyle=Relief reliefexpansion=10 reliefentries=4 reliefconductorwidth=10 reliefairgap=10
PolygonConnect [All] p0: scope1count=1 scope1_0_kind=Board scope1_0_value=Board scope2count=1 scope2_0_kind=Board scope2_0_value=Board commentlength=0 connectstyle=Direct reliefconductorwidth=10 reliefentries=4 polygonreliefangle="90 Angle"
PolygonConnect [All] p1: connectstyle=Direct reliefconductorwidth=10 reliefentries=4 polygonreliefangle="90 Angle" airgapwidth=10
RoomDefinition BGA1 [All] p0 off: scope1count=1 scope1_0_kind=Board scope1_0_value=Board scope2count=1 scope2_0_kind=Board scope2_0_value=Board commentlength=57 region_x1=23660000 region_y1=31370000 region_x2=36912838 region_y2=46780017 confinementstyle=ConfineIn // Protel DXP Scope 1 Expression Was: WithinRoom('BGA1')
RoomDefinition BGA1 [WithinRoom('BGA1')] p1: confinementstyle=ConfineIn formatcopy=TRUE lockcomponents=FALSE outline 830,2673.77 1999.28,2673.77 1999.28,1914.05 1921,1835.77 1921,1801.77 1663,1543.77 1415,1543.77 1414,1542.77 1414,1369.77 1477,1306.77 1477,1222.77 1467,1212.77 1435,1212.77 1418,1195.77 1362,1195.77 1362,1149.77 1345,1132.77 1266,1132.77 1256,1142.77 1256,1176.77 1224,1208.77 1190,1208.77 1177,1221.77 1177,1262.77 1084,1355.77 904,1355.77 839,1420.77 839,1566.77 807,1598.77 729,1598.77 711,1580.77 681,1580.77 674,1587.77 674,1680.77 678,1684.77 808,1684.77 844,1720.77 844,1917.77 830,1931.77
RoutingCorners [All] p0: scope1count=1 scope1_0_kind=Board scope1_0_value=Board scope2count=1 scope2_0_kind=Board scope2_0_value=Board commentlength=0 cornerstyle=45-Degree minsetback=100 maxsetback=100
RoutingLayers [All] p0: scope1count=1 scope1_0_kind=Board scope1_0_value=Board scope2count=1 scope2_0_kind=Board scope2_0_value=Board commentlength=0 top layer=Automatic mid layer 1=Automatic mid layer 2=Automatic mid layer 3=Automatic mid layer 4=Automatic mid layer 5=Automatic mid layer 6=Automatic bottom layer=Automatic
RoutingPriority [All] p0: scope1count=1 scope1_0_kind=Board scope1_0_value=Board scope2count=1 scope2_0_kind=Board scope2_0_value=Board commentlength=0
RoutingTopology [All] p0: scope1count=1 scope1_0_kind=Board scope1_0_value=Board scope2count=1 scope2_0_kind=Board scope2_0_value=Board commentlength=0 topology=Shortest
RoutingVias ThermalPadVias [All] p0 off: scope1count=1 scope1_0_kind=Board scope1_0_value=Board scope2count=1 scope2_0_kind=Board scope2_0_value=Board commentlength=63 holewidth=7.87 width=19.68 viastyle="Through Hole" minholewidth=5 minwidth=13 maxholewidth=12.99 maxwidth=23.62 // Protel DXP Scope 1 Expression Was: IsVia and InAnyComponent
RoutingVias [All] p0: scope1count=1 scope1_0_kind=Board scope1_0_value=Board scope2count=1 scope2_0_kind=Board scope2_0_value=Board commentlength=0 holewidth=12.2 width=22.4 viastyle="Through Hole" minholewidth=5.9 minwidth=15.74 maxholewidth=20 maxwidth=40
RoutingVias ThermalPadVias [IsVia and InAnyComponent] p1: holewidth=7.87 width=19.68 viastyle="Through Hole" minholewidth=5 minwidth=13 maxholewidth=12.99 maxwidth=23.62
RoutingVias [All] p2: holewidth=12.2 width=22.4 viastyle="Through Hole" minholewidth=5.9 minwidth=15.74 maxholewidth=20 maxwidth=40
SMDToCorner [All] p0: scope1count=1 scope1_0_kind=Board scope1_0_value=Board scope2count=1 scope2_0_kind=Board scope2_0_value=Board commentlength=0 distance=25000
SMDToCorner [All] p1: distance=25000
ShortCircuit [All] p0: scope1count=1 scope1_0_kind=Board scope1_0_value=Board scope2count=1 scope2_0_kind=Board scope2_0_value=Board commentlength=0 allowed=FALSE
SilkToBoardRegionClearance [All] p0 off: scope1count=1 scope1_0_kind=Board scope1_0_value=Board scope2count=1 scope2_0_kind=Board scope2_0_value=Board commentlength=130 // Protel DXP Scope 1 Expression Was: Not ((IsComment or IsDesignator) And (Hide <> 'False')) and not InRegion(1000,500,4000,800)
SilkToBoardRegionClearance [Not ((IsComment or IsDesignator) And (Hide <> 'False')) and not InRegion(1000,500,4000,800)] p1:
SilkToSilkClearance [All] p0: scope1count=1 scope1_0_kind=Board scope1_0_value=Board scope2count=1 scope2_0_kind=Board scope2_0_value=Board commentlength=0
SilkToSilkClearance [All] p1: silktosilkclearance=3
SilkToSolderMaskClearance SilkToSolderMaskClearance_OutLine [All] p0 off: scope1count=1 scope1_0_kind=Board scope1_0_value=Board scope2count=1 scope2_0_kind=Board scope2_0_value=Board commentlength=65 // Protel DXP Scope 1 Expression Was: istrack and InAnyComponent
SilkToSolderMaskClearance SilkscreenOverComponentPads [All] p0 off: scope1count=1 scope1_0_kind=Board scope1_0_value=Board scope2count=1 scope2_0_kind=Board scope2_0_value=Board commentlength=44 // Protel DXP Scope 1 Expression Was: IsPad
SilkToSolderMaskClearance SilkToSolderMaskClearance_OutLine [istrack and InAnyComponent] p1: minsilkscreentomaskgap=0 clearancetoexposedcopper=FALSE
SilkToSolderMaskClearance SilkscreenOverComponentPads [IsPad] p2: minsilkscreentomaskgap=3 clearancetoexposedcopper=FALSE
SolderMaskExpansion [All] p0: scope1count=1 scope1_0_kind=Board scope1_0_value=Board scope2count=1 scope2_0_kind=Board scope2_0_value=Board commentlength=0 expansion=0
SolderMaskExpansion [All] p1: expansion=0
UnRoutedNet [All] p0: scope1count=1 scope1_0_kind=Board scope1_0_value=Board scope2count=1 scope2_0_kind=Board scope2_0_value=Board commentlength=0
UnpouredPolygon [All] p0: scope1count=1 scope1_0_kind=Board scope1_0_value=Board scope2count=1 scope2_0_kind=Board scope2_0_value=Board commentlength=0
Width [All] p0: scope1count=1 scope1_0_kind=Board scope1_0_value=Board scope2count=1 scope2_0_kind=Board scope2_0_value=Board commentlength=0 maxlimit=100 minlimit=4 preferedwidth=6
Width [All] p1: maxlimit=100 minlimit=4 preferedwidth=6
13 further rules are at their usual default settings.

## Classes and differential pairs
net class LVDS: NetJ1_28 NetJ1_30 NetJ1_34 NetJ1_36 NetJ1_40 NetJ1_42 NetJ1_46 NetJ1_48 NetJ2_21 NetJ2_23 NetJ2_27 NetJ2_29 NetJ2_39 NetJ2_41 NetJ6_20 NetJ6_22 NetJ6_26 NetJ6_28 NetJ6_32 NetJ6_34 NetJ6_38 NetJ6_40 NetJ6_44 NetJ6_46 NetJ6_50 NetJ6_52 NetJ6_56 NetJ6_58 RADAR_LVDS_0M RADAR_LVDS_0P RADAR_LVDS_1M RADAR_LVDS_1P RADAR_LVDS_2M RADAR_LVDS_2P RADAR_LVDS_3M RADAR_LVDS_3P RADAR_LVDS_CLKM RADAR_LVDS_CLKP RADAR_LVDS_FRCLKM RADAR_LVDS_FRCLKP RADAR_LVDS_VALIDM RADAR_LVDS_VALIDP
net class 1A: CB_PMIC_1V0 CB_PMIC_1V2 CB_PMIC_1V8 PMIC_1V0 PMIC_1V2 PMIC_1V8 PMIC_3V3 RADAR_1P0_RF1 RADAR_1P0_RF2 RADAR_1V2 RADAR_1V8 RADAR_3V3 VCC_LD_SW_3V3
pad class "Mounting Holes PADS": Free-TH1 Free-TH2 Free-TH3 Free-TH4 Free-TH5 Free-TH6 Free-TH7 Free-TH8 Free-TH9
net class "Diff Pairs": NetJ1_28 NetJ1_30 NetJ1_34 NetJ1_36 NetJ1_40 NetJ1_42 NetJ1_46 NetJ1_48 RADAR_LVDS_0M RADAR_LVDS_0P RADAR_LVDS_1M RADAR_LVDS_1P RADAR_LVDS_CLKM RADAR_LVDS_CLKP RADAR_LVDS_FRCLKM RADAR_LVDS_FRCLKP
component class Logo: Logo1 Logo5
component class FiducialMark: FID1 FID2 FID3 FID4 FID5 FID6
component class Label: LBL1
component class PROC073C_Decoupling_caps: C1 C2 C3 C4 C5 C6 C7 C8 C9 C10 C11 C12 C13 C14 C15 C16 C17 C18 C19 C20 C21 C22 C23 C24 C25 C26 C27 C28 C29 C30 C64 C76 C77 C78 C79 C80 C81 C82 C83 L1 L2 L3 L7 R1
component class PROC073C_EVM_Hardware: "CAUTION HOT SURFACE1" FID1 FID2 FID3 FID4 FID5 FID6 LBL1 Logo1 Logo2 LOGO3 Logo4 Logo5 ZZ1 ZZ2 ZZ3 ZZ4 ZZ5
component class PROC073C_HD_Connector_60Pin: J1 J2 R4 R5 R6 R7 R8 R9 R10 R11 R12 R13 R15 R16 R17 R18 R19 R20 R21 R22 R23 R24 R26 R27 R28 R30 R31 R32 R33 R34 R35 R36 R37 R38 R39 R40 R41 R42 R52 R53 R58 R59 R60 R61 R62 R63 R64 R65 R66 R67 R124 R125 R126 R127 R128 R129 R130 R131 R132 R133 R134 R135 R136 R137 R140 TP14
component class PROC073C_IWR6843_Chip: C31 C32 C33 R72 R73 R74 R75 R76 R77 R150 R152 R153 R154 R155 R156 R169 TP2 TP3 TP4 TP5 TP6 TP7 U1 Y1
component class PROC073C_Can_Interface: C37 C38 C39 C40 C41 C42 C43 J3 J4 R3 R68 R69 R70 R71 R78 R79 R80 R81 R82 R83 R84 R85 R86 R87 R88 R89 R216 U5 U12 U13
component class PROC073C_QSPI_Flash_section: C34 C35 R43 R44 R45 R46 R47 R48 R49 R50 R51 U2
component class PROC073C_Temp_Current_sensor: C36 C57 C58 C59 C63 C65 R2 R14 R25 R29 R54 R55 R56 R57 R94 R101 R103 R104 R105 R106 R107 R108 R109 R110 R111 R112 R113 R114 R115 R116 R117 R139 R142 R143 R144 R145 R146 R147 R151 R157 R158 R159 R160 R161 R162 U3 U6 U7 U8 U10 U11
net class "TX and RX": RX1 RX2 RX3 RX4 TX1 TX2 TX3
component class AssemblyNote: ZZ1 ZZ2 ZZ3 ZZ4 ZZ5
net class Flash: RADAR_QSPI_CS RADAR_QSPI_D0 RADAR_QSPI_D1 RADAR_QSPI_D2 RADAR_QSPI_D3 RADAR_QSPI_SCLK
component class PROC073C_Flash_USB_To_UART: C44 C45 C46 C47 C48 C49 C50 C51 D1 D2 D4 FL1 FL2 J5 L9 L10 LD1 R90 R91 R92 R93 R95 R96 R97 R98 R99 R100 R102 R118 R119 R120 R121 TP1 TP8 U14 U15 U16
component class PROC073C_HD_DCA_Conn: C52 C53 D5 D7 J6 LD2 LD4 Q1 R122 R123 R138 R141 R148 R149 R163 R164 R165 R166 R167 R168 R170 R171 R212 R213 R214 R215 R217 R218 R219 R220 R221 R222 R223 R224 R225 R226 R227 R228 R229 R230 S2 S3 SW1 SW2 TP12 TP13 U17
component class PROC073C_PMIC: C54 C55 C56 C60 C61 C62 C66 C67 C68 C69 C70 C71 C72 C73 C74 C75 D3 D6 FL3 FL4 L4 L5 L6 L8 L11 L12 LD3 Q2 R172 R173 R174 R175 R176 R177 R178 R179 R180 R181 R182 R183 R184 R185 R186 R187 R188 R189 R190 R191 R192 R193 R194 R195 R196 R197 R198 R199 R200 R201 TP9 TP10 TP11 U4 U9
component class PROC073C_SOP_Ctrl: R202 R203 R204 R205 R206 R207 R208 R209 R210 R211 S1
differential pair NewDifferentialPair21: +NetJ6_38 -NetJ6_40
differential pair NewDifferentialPair20: +RADAR_LVDS_2P -RADAR_LVDS_2M
differential pair NewDifferentialPair19: +NetJ2_23 -NetJ2_21
differential pair NewDifferentialPair18: +NetJ6_32 -NetJ6_34
differential pair NewDifferentialPair17: +RADAR_LVDS_3P -RADAR_LVDS_3M
differential pair NewDifferentialPair16: +NetJ2_29 -NetJ2_27
differential pair NewDifferentialPair15: +NetJ2_41 -NetJ2_39
differential pair NewDifferentialPair14: +RADAR_LVDS_VALIDP -RADAR_LVDS_VALIDM
differential pair NewDifferentialPair13: +NetJ6_20 -NetJ6_22
differential pair NewDifferentialPair12: +NetJ6_28 -NetJ6_26
differential pair NewDifferentialPair11: +NetJ6_44 -NetJ6_46
differential pair NewDifferentialPair10: +NetJ6_52 -NetJ6_50
differential pair NewDifferentialPair9: +NetJ6_58 -NetJ6_56
differential pair NewDifferentialPair8: +NetJ1_30 -NetJ1_28
differential pair NewDifferentialPair7: +NetJ1_36 -NetJ1_34
differential pair NewDifferentialPair6: +NetJ1_42 -NetJ1_40
differential pair NewDifferentialPair5: +NetJ1_48 -NetJ1_46
differential pair NewDifferentialPair4: +RADAR_LVDS_FRCLKM -RADAR_LVDS_FRCLKP
differential pair NewDifferentialPair3: +RADAR_LVDS_CLKM -RADAR_LVDS_CLKP
differential pair NewDifferentialPair2: +RADAR_LVDS_1M -RADAR_LVDS_1P
differential pair " ": +RADAR_LVDS_0M -RADAR_LVDS_0P

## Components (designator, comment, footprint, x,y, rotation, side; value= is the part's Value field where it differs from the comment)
C1 "CGA5L1X7R0J226M160AC" 1206_180 1230.15,1083.72 r180 bottom
C2 "CGA5L1X7R0J226M160AC" 1206_180 1021.11,2369.87 r270 bottom
C3 "CGA5L1X7R0J226M160AC" 1206_180 882.8,2049.32 r90 bottom
C4 "GCM155R71C224KE02D" 0402L 1374.59,1781.77 r270 top
C5 "GCM155R71C224KE02D" 0402L 1419.18,1456.18 r180 top
C6 "GCM155R71C224KE02D" 0402L 1325,1514.77 r180 bottom
C7 "C0805C106M8RACTU" 0805_HV 1495.59,1784.77 r180 bottom
C8 "C0805C106M8RACTU" 0805_HV 1495.59,1894.77 r180 bottom
C9 "GCM155R71C224KE02D" 0402L 1200,1369.77 r90 bottom
C10 "GCM155R71C224KE02D" 0402L 960.59,1574.77 r180 bottom
C11 "GCM155R71C224KE02D" 0402L 1007.18,1761.18 r270 bottom
C12 "GCM155R71C224KE02D" 0402L 1181.59,1733.77 r180 bottom
C13 "C0805C106M8RACTU" 0805_HV 1183.59,1793.77 r180 bottom
C14 "GCM155R71C224KE02D" 0402L 1505.59,1454.77 r180 top
C15 "C0805C106M8RACTU" 0805_HV 1615,1449.77 r270 top
C16 "GCM155R71C224KE02D" 0402L 1163.59,1224.77 r90 top
C17 "GCM188R70J225KE22D" 0603 800.59,1584.77 r0 top
C18 "GCM188R71C105KA64D" 0603 1436.78,1381.18 r180 top
C19 "GCM155R71C224KE02D" 0402L 1049.18,1761.18 r270 bottom
C20 "GCM155R71C224KE02D" 0402L 1346.59,1854.77 r180 bottom
C21 "GCM155R71C224KE02D" 0402L 806.59,1535.77 r0 top
C22 "GCM188R71C105KA64D" 0603 1440.59,1524.77 r180 top
C23 "C0805C106M8RACTU" 0805_HV 1030.59,1879.77 r90 bottom
C24 "C0805C106M8RACTU" 0805_HV 1345.59,1764.77 r180 bottom
C25 "GCM155R71C104KA55D" 0402L 875.59,1314.77 r0 top
C26 "GCM155R71C104KA55D" 0402L 1134.5,1300.77 r90 top
C27 "GCM188R70J225KE22D" 0603 810.59,1364.77 r0 top
C28 "GCM155R71C224KE02D" 0402L 850.59,1669.77 r0 top
C29 "GCM155R71C224KE02D" 0402L 980.59,1514.77 r270 bottom
C30 "GCM155R71E103KA37D" 0402L 1105,1324.77 r270 bottom
C31 "GRM033C71A104KE14D" 0201 1049.59,1421.77 r90 bottom
C32 "GJM1555C1H4R7BB01D" 0402L 1435.59,1274.77 r90 top
C33 "GJM1555C1H4R7BB01D" 0402L 1315.59,1179.77 r180 top
C34 "CGA2B3X7R1H104K050BB" 0402L 635.7,926.67 r180 top
C35 "GCM188R71C105KA64D" 0603 647.51,860.63 r180 top
C36 "CGA2B3X7R1H104K050BB" 0402L 900,954.77 r90 bottom
C37 "C0402C104K8RACTU" 0402L 371.69,472.72 r90 bottom
C38 "C0402C104K8RACTU" 0402L 265.63,589.74 r180 top
C39 "GCM155R71H472KA37D" 0402L 179.95,450.74 r0 bottom
C40 "C0402C104K8RACTU" 0402L 293.22,255.44 r90 bottom
C41 "C0402C104K8RACTU" 0402L 265.64,325.13 r180 bottom
C42 "GCM155R71H472KA37D" 0402L 166.99,131.4 r0 bottom
C43 "C0402C104K8RACTU" 0402 682.22,726.76 r90 top
C44 "GRM033R6YA104KE14D" "FP-GRM033R6YA104KE14D_0201 (0603 Metric)-IPC_C" 1886.12,301.92 r180 top
C45 "GRM033R6YA104KE14D" "FP-GRM033R6YA104KE14D_0201 (0603 Metric)-IPC_C" 1886.12,328.23 r180 top
C46 "CL05A106MP5NUNC" 0402_070 1789.78,82.28 r270 top
C47 "CL05A106MP5NUNC" 0402_070 1828.84,82.28 r90 top
C48 "GRM033R6YA104KE14D" "FP-GRM033R6YA104KE14D_0201 (0603 Metric)-IPC_C" 1882.6,543.11 r270 top
C49 "GRM033R6YA104KE14D" "FP-GRM033R6YA104KE14D_0201 (0603 Metric)-IPC_C" 1656.37,490.4 r270 top
C50 "GRM033R6YA104KE14D" "FP-GRM033R6YA104KE14D_0201 (0603 Metric)-IPC_C" 1610.54,622.77 r180 top
C51 "CL03A105MO3NRNH" FP-CL03A105MO3NRNH_0201-IPC_C 1704.92,566.28 r270 top
C52 "GRM033R6YA104KE14D" "FP-GRM033R6YA104KE14D_0201 (0603 Metric)-IPC_C" 639.02,1351.06 r0 top
C53 "GRM033R6YA104KE14D" "FP-GRM033R6YA104KE14D_0201 (0603 Metric)-IPC_C" 571.56,1307.45 r0 top
C54 "TMK063CG391JT-F" "FP-TMK063CG391JT-F_0201 (0603 Metric)-IPC_C" 854.8,481.54 r270 top
C55 "TMK063CG391JT-F" "FP-TMK063CG391JT-F_0201 (0603 Metric)-IPC_C" 1144.8,480.89 r270 top
C56 "TMK063CG391JT-F" "FP-TMK063CG391JT-F_0201 (0603 Metric)-IPC_C" 857.9,767.9 r270 top
C57 "CGA2B3X7R1H104K050BB" 0402L 1253.55,632.76 r180 top
C58 "CGA2B3X7R1H104K050BB" 0402L 672.08,1973.74 r90 bottom
C59 "CGA2B3X7R1H104K050BB" 0402L 810.31,940.08 r0 bottom
C60 "TMK063CG391JT-F" "FP-TMK063CG391JT-F_0201 (0603 Metric)-IPC_C" 1139.71,770.25 r270 top
C61 "CL05A226MQ5N6J8" "FP-CL05A226MQ5N6J8_0402 (1005 Metric)-IPC_C" 984.51,413.06 r90 top
C62 "CL05A226MQ5N6J8" "FP-CL05A226MQ5N6J8_0402 (1005 Metric)-IPC_C" 1016.73,413.53 r90 top
C63 "CGA2B3X7R1H104K050BB" 0402L 898.74,1417.96 r180 bottom
C64 "CGA5L1X7R0J226M160AC" 1206_180 554.85,2199.7 r0 bottom
C65 "CGA2B3X7R1H104K050BB" 0402L 475,2434.77 r0 bottom
C66 "CL05A226MQ5N6J8" "FP-CL05A226MQ5N6J8_0402 (1005 Metric)-IPC_C" 983.42,868.35 r270 top
C67 "CL05A226MQ5N6J8" "FP-CL05A226MQ5N6J8_0402 (1005 Metric)-IPC_C" 1015.86,868.35 r270 top
C68 "LMK063BJ224MP-F" 0201_033L 1112.94,634.48 r270 top
C69 "CL10B105KQ8NNNC" 0603 763.67,1037.97 r270 top
C70 "C0603C104J5RACTU" 0603 708.74,1344.77 r90 top
C71 "CGA2B3X7S2A102K050BB" 0402 933.74,1224.77 r270 top
C72 "CL05A106MP5NUNC" 0402_070 1031.96,760.63 r180 top
C73 "CL05A106MP5NUNC" 0402_070 1031.68,510.63 r180 top
C74 "CL05A106MP5NUNC" 0402_070 969.08,760.63 r0 top
C75 "CL05A106MP5NUNC" 0402_070 969.08,510.63 r0 top
C76 "GCM32ER71C226KE19L" 1210_280 1380.16,2039.19 r0 bottom
C77 "GCM21BR71A106KE22L" 0805_HV 1355.2,2148.45 r0 bottom
C78 "GCM32ER71C226KE19L" 1210_280 1148.04,2157.85 r90 bottom
C79 "GCM21BR71A106KE22L" 0805_HV 1034.97,2132.89 r90 bottom
C80 "GCM32ER71C226KE19L" 1210_280 809.39,1895.19 r0 bottom
C81 "GCM21BR71A106KE22L" 0805_HV 744.63,2195.15 r0 bottom
C82 "GCM32ER71C226KE19L" 1210_280 1118.27,835.48 r0 bottom
C83 "GCM21BR71A106KE22L" 0805_HV 1102.93,977.35 r0 bottom
"CAUTION HOT SURFACE1" "CAUTION HOT SURFACE" IEC_HotSurface_Small 678.45,2381.29 r0 top
D1 "NSR20F30NXT5G" DSN2_0603 1927.08,61.77 r0 top
D2 "NSR20F30NXT5G" DSN2_0603 1756.62,604.69 r90 top
D3 "TLMY1000-GS08" TLMx1000_Yellow 650.96,457.8 r180 top
D4 "APHHS1005CGCK" APHHS1005_Green 1604.25,245.51 r270 top
D5 "APHHS1005CGCK" APHHS1005_Green 345.96,1420.88 r90 top
D6 "APHHS1005CGCK" APHHS1005_Green 1274.62,480.04 r180 top
D7 "APHHS1005CGCK" APHHS1005_Green 1875.31,1620.81 r0 top
FID1 "Fiducial" Fiducial10-20 294.16,2411.14 r90 top
FID2 "Fiducial" Fiducial10-20 2091.36,479.28 r90 bottom
FID3 "Fiducial" Fiducial10-20 70.7,298.59 r90 bottom
FID4 "Fiducial" Fiducial10-20 70.7,298.59 r90 top
FID5 "Fiducial" Fiducial10-20 294.16,2411.14 r90 bottom
FID6 "Fiducial" Fiducial10-20 2091.36,479.28 r90 top
J1 "QSH-030-01-L-D-A" Samtec_QSH-030-01-X-D-A 1708.74,1109.77 r0 bottom locked
J2 "QSH-030-01-L-D-A" Samtec_QSH-030-01-X-D-A 417.24,1109.77 r0 bottom locked
J3 "M50-3930342" FP-M50-3930342_HDR3-MFG 47.76,448.74 r270 top
J4 "M50-3930342" FP-M50-3930342_HDR3-MFG 47.76,131.4 r270 top
J5 "105017-0001" CONN_105017-0001 2055.12,201.38 r90 top
J6 "QSH-030-01-L-D-A" Samtec_QSH-030-01-X-D-A 1219.74,230.48 r270 bottom locked
L1 "MPZ2012S101A" MPZ2012 1087.23,1094.15 r270 bottom
L2 "MPZ2012S101A" MPZ2012 1171.01,2302.94 r0 bottom
L3 "MPZ2012S101A" MPZ2012 999.54,2008.62 r0 bottom
L4 "MCKK2012TR47M" "FP-MCKK2012TR47M_0805 (2012 Metric)-IPC_C" 935.96,434.56 r90 top
L5 "MCKK2012TR47M" "FP-MCKK2012TR47M_0805 (2012 Metric)-IPC_C" 1064.7,434.56 r90 top
L6 "MCKK2012TR47M" "FP-MCKK2012TR47M_0805 (2012 Metric)-IPC_C" 935.96,834.4 r270 top
L7 "MPZ2012S101A" MPZ2012 669.33,2114.23 r0 bottom
L8 "MCKK2012TR47M" "FP-MCKK2012TR47M_0805 (2012 Metric)-IPC_C" 1064.7,834.4 r270 top
L9 "BLM15PD300SZ1D" 0402L 1937.91,130.51 r270 top
L10 "BLM15PD300SZ1D" 0402L 1675.47,595.84 r90 top
L11 "BLM15PD300SZ1D" 0402L 1937.18,419.58 r0 top
L12 "BLM15PD300SZ1D" 0402L 863.92,409.21 r0 top
LBL1 "THT-14-423-10" Label_650x200 448.64,2105.95 r90 top
Logo1 "Texas Instruments" TI_Stacked_Overlay_Small 1726.87,1037.15 r0 top
Logo2 "CE Mark" CE_Mark_5mm 1000.93,515.95 r180 bottom
LOGO3 "FCC disclaimer" FCC_disclaimer 966.67,2489.6 r180 bottom (schematic designator Logo3)
Logo4 "WEEE logo" WEEE_Minimum 1836.06,549.11 r180 bottom
Logo5 "Texas Instruments" TI_Symbol_Overlay_Small 1337.21,2358.31 r180 bottom
Q1 "BSS123-7-F" FP-BSS123-7-F_SOT23-IPC_C 434.95,1438.6 r180 top
Q2 "BSS123" SOT-23 658.67,326 r180 top
R1 "MCT06030Z0000ZP500" 0603 1355.59,1939.77 r0 bottom
R2 "CRCW040210K0FKED" 0402L 1215.81,813.9 r90 top
R3 "ERJ-2GE0R00X" 0402 350.51,392.41 r0 bottom
R4 "CRCW02010000Z0ED" 0201_Silk 1424.97,923.97 r180 bottom
R5 "CRCW02010000Z0ED" 0201_Silk 1425.43,810.89 r0 bottom
R6 "CRCW02010000Z0ED" 0201_Silk 1425.43,880.18 r180 bottom
R7 "CRCW02010000Z0ED" 0201_Silk 1614.76,935.2 r0 top
R8 "CRCW02010000Z0ED" 0201_Silk 1425.43,845.53 r180 bottom
R9 "CRCW02010000Z0ED" 0201_Silk 1443.74,958.34 r0 bottom
R10 "CRCW02010000Z0ED" 0201_Silk 1844.67,950.58 r180 top
R11 "CRCW02010000Z0ED" 0201_Silk 1614.76,975.28 r0 top
R12 "CRCW02010000Z0ED" 0201_Silk 1614.76,1015.36 r180 top
R13 "CRCW02010000Z0ED" 0201_Silk 1932.36,967.82 r0 bottom
R14 "CRCW040210K0FKED" 0402L 1301.47,833.15 r270 bottom
R15 "CRCW020120R0FNED" 0201_033 1889.86,914.52 r0 top
R16 "CRCW02010000Z0ED" 0201_Silk 1964.4,1109.48 r90 bottom
R17 "CRCW020120R0FNED" 0201_033 1889.86,876.15 r0 top
R18 "CRCW020120R0FNED" 0201_033 1614.76,1055.44 r0 top
R19 "CRCW020120R0FNED" 0201_033 1448.74,1026.09 r0 bottom
R20 "CRCW020120R0FNED" 0201_033 1383.28,1042.27 r0 bottom
R21 "CRCW020120R0FNED" 0201_033 1614.76,1095.52 r0 top
R22 "CRCW02010000Z0ED" 0201_Silk 1863.79,1052.42 r180 top
R23 "CRCW020120R0FNED" 0201_033 1443.74,1062.27 r0 bottom
R24 "CRCW02010000Z0ED" 0201_Silk 1863.79,1087.42 r180 top
R25 "CRCW02010000Z0ED" 0201 1229.01,926.07 r90 top
R26 "CRCW020120R0FNED" 0201_033 1443.74,1096.91 r0 bottom
R27 "CRCW020120R0FNED" 0201_033 1448.74,1131.56 r0 bottom
R28 "CRCW020120R0FNED" 0201_033 1448.74,1166.2 r0 bottom
R29 "CRCW02010000Z0ED" 0201 1267.18,926.07 r90 top
R30 "CRCW02010000Z0ED" 0201_Silk 1863.79,1136.89 r180 top
R31 "CRCW02010000Z0ED" 0201_Silk 1932.36,1005.51 r0 bottom
R32 "CRCW02010000Z0ED" 0201_Silk 1863.79,1171.89 r180 top
R33 "CRCW02010000Z0ED" 0201_Silk 1863.79,1232.24 r180 top
R34 "CRCW02010000Z0ED" 0201_Silk 1475,1421.77 r0 bottom
R35 "CRCW02010000Z0ED" 0201_Silk 1863.79,1270.22 r180 top
R36 "CRCW02010000Z0ED" 0201_Silk 1845.35,988.39 r180 top
R37 "CRCW02010000Z0ED" 0201_Silk 1515,1455.77 r0 bottom
R38 "CRCW02010000Z0ED" 0201_Silk 1725,1579.77 r180 bottom
R39 "CRCW02010000Z0ED" 0201_Silk 1863.79,1334.43 r180 top
R40 "CRCW02010000Z0ED" 0201_Silk 1725,1614.77 r180 bottom
R41 "CRCW02010000Z0ED" 0201_Silk 1863.79,1372.41 r180 top
R42 "CRCW02010000Z0ED" 0201_Silk 1932.38,930.27 r180 bottom
R43 "ERJ-2GE0R00X" 0402 553.88,854.79 r270 top
R44 "CRCW040210K0FKED" 0402L 418.88,1290.23 r90 top
R45 "CRCW020133R2FNED" 0201_Silk 403.88,847.19 r270 top
R46 "CRCW020133R2FNED" 0201_Silk 503.88,1211.1 r270 top
R47 "CRCW020133R2FNED" 0201_Silk 453.88,1211.1 r270 top
R48 "CRCW020133R2FNED" 0201_Silk 453.88,847.19 r270 top
R49 "CRCW040210K0FKED" 0402L 523.57,786.64 r0 top
R50 "CRCW040247K5FKED" 0402L 553.88,1212.19 r270 top
R51 "CRCW020133R2FNED" 0201_Silk 503.88,847.19 r270 top
R52 "CRCW040210K0FKED" 0402L 809.93,980.11 r0 bottom
R53 "CRCW040210K0FKED" 0402L 768.74,1109.77 r90 bottom
R54 "CRCW040210K0FKED" 0402L 943.74,1139.77 r90 bottom
R55 "CRCW02010000Z0ED" 0201 839.48,1021.13 r0 bottom
R56 "CRCW02010000Z0ED" 0201 843.74,1094.77 r0 bottom
R57 "CRCW04020000Z0ED" 0402 990.93,896.1 r270 bottom
R58 "CRCW02010000Z0ED" 0201_Silk 1931.3,1316.46 r0 bottom
R59 "CRCW02010000Z0ED" 0201_Silk 1931.3,1354.7 r0 bottom
R60 "CRCW02010000Z0ED" 0201_Silk 1448.74,1200.84 r180 bottom
R61 "CRCW02010000Z0ED" 0201_Silk 1448.74,1235.48 r180 bottom
R62 "CRCW02010000Z0ED" 0201_Silk 1448.74,1270.13 r180 bottom
R63 "CRCW02010000Z0ED" 0201_Silk 1448.74,1304.77 r180 bottom
R64 "CRCW02010000Z0ED" 0201_Silk 1475,1387.77 r180 bottom
R65 "CRCW02010000Z0ED" 0201_Silk 1970,1559.77 r270 bottom
R66 "CRCW02010000Z0ED" 0201_Silk 1935,1559.77 r90 bottom
R67 "CRCW02010000Z0ED" 0201_Silk 1900,1559.77 r90 bottom
R68 "CRCW040261R9FKED" 0402L 179.95,400.74 r180 bottom
R69 "CRCW02010000Z0ED" 0201_Silk 371.69,544.66 r90 bottom
R70 "CRCW040210K0FKED" 0402L 326.89,459.91 r270 bottom
R71 "CRCW040210K0FKED" 0402L 292.59,459.91 r90 bottom
R72 "ERJ-2GE0R00X" 0402 800.59,1949.77 r0 top
R73 "ERJ-2GE0R00X" 0402 800.59,1904.77 r0 top
R74 "ERJ-2GE0R00X" 0402 800.59,1814.77 r0 top
R75 "ERJ-2GE0R00X" 0402 800.59,1859.77 r0 top
R76 "ERJ-2GE0R00X" 0402 1490,1269.77 r90 top
R77 "ERJ-2GE0R00X" 0402 1268.74,1129.77 r180 top
R78 "ERJ-2GE0R00X" 0402 542.39,415.71 r270 bottom
R79 "CRCW040261R9FKED" 0402L 179.95,500.74 r0 bottom
R80 "ERJ-2GE0R00X" 0402 547.5,542.41 r180 top
R81 "CRCW040261R9FKED" 0402L 166.99,81.4 r180 bottom
R82 "CRCW02010000Z0ED" 0201_Silk 256.48,262.14 r270 bottom
R83 "CRCW040210K0FKED" 0402L 549.57,180.17 r270 top
R84 "CRCW040210K0FKED" 0402L 587.71,180.16 r90 top
R85 "ERJ-2GE0R00X" 0402 469.06,180.13 r180 top
R86 "CRCW040261R9FKED" 0402L 166.99,181.4 r0 bottom
R87 "ERJ-2GE0R00X" 0402 469.06,325.13 r180 top
R88 "CRCW040210K0FKED" 0402L 638.24,724.69 r90 top
R89 "CRCW04024K70JNED" 0402 755.42,695.23 r270 top
R90 "RC0201FR-074K99L" 0201L 1780.23,424.98 r270 top
R91 "RC0201JR-070RL" "FP-RC0201JR-070RL_0201 (0603 Metric)-MFG" 1945.7,209.97 r0 top
R92 "RC0201JR-070RL" "FP-RC0201JR-070RL_0201 (0603 Metric)-MFG" 1945.7,183.31 r0 top
R93 "RC0201FR-074K99L" 0201L 1702.37,418.68 r270 top
R94 "CRCW040210K0FKED" 0402L 1303.87,932.76 r270 top
R95 "RR0306P-103-D" FP-RR0306P-103-D_0201-IPC_C 1752.9,424.47 r270 top
R96 "RC0201JR-070RL" "FP-RC0201JR-070RL_0201 (0603 Metric)-MFG" 1693.49,145.26 r180 top
R97 "RC0201JR-070RL" "FP-RC0201JR-070RL_0201 (0603 Metric)-MFG" 1594.82,351.37 r180 top
R98 "RC0201JR-070RL" "FP-RC0201JR-070RL_0201 (0603 Metric)-MFG" 1594.82,322.25 r0 top
R99 "RC0201JR-07220RL" 0201L 1615.28,183.64 r180 top
R100 "RR0306P-103-D" FP-RR0306P-103-D_0201-IPC_C 1912.81,668.16 r0 top
R101 "CRCW040210K0FKED" 0402L 1182.13,813.87 r270 top
R102 "RR0306P-103-D" FP-RR0306P-103-D_0201-IPC_C 1397.73,582.46 r0 top
R103 "CRCW040210K0FKED" 0402L 1266.47,833.15 r90 bottom
R104 "CRCW040210K0FKED" 0402L 378.85,1779.32 r180 bottom
R105 "CRCW040210K0FKED" 0402L 378.85,1742.89 r180 bottom
R106 "CRCW040210K0FKED" 0402L 634.64,726.36 r180 bottom
R107 "CRCW040210K0FKED" 0402L 674.01,645.31 r0 bottom
R108 "CRCW02010000Z0ED" 0201 542.98,2060.58 r90 bottom
R109 "CRCW02010000Z0ED" 0201 715,1024.77 r0 bottom
R110 "CRCW02010000Z0ED" 0201 577.98,2060.58 r90 bottom
R111 "CRCW02010000Z0ED" 0201 715,989.77 r0 bottom
R112 "CRCW040210K0FKED" 0402L 378.85,1961.46 r0 bottom
R113 "CRCW040210K0FKED" 0402L 378.85,1815.75 r0 bottom
R114 "CRCW040210K0FKED" 0402L 378.85,1706.46 r0 bottom
R115 "CRCW040210K0FKED" 0402L 636.16,1004.04 r270 bottom
R116 "CRCW040210K0FKED" 0402L 634.63,762.57 r0 bottom
R117 "CRCW040210K0FKED" 0402L 634.63,690.14 r0 bottom
R118 "RC0201JR-07510RL" 0201L 1555.79,634.76 r180 top
R119 "CRCW0201100KFKED" 0201L 1467.08,593.51 r90 top
R120 "CRCW0201100KFKED" 0201L 1432.23,593.51 r270 top
R121 "CRCW0402200RFKEDHP" FP-CRCW0402200RFKEDHP_0402-IPC_C 1438.41,478.28 r0 top
R122 "ERJ-2GE0R00X" 0402L 729.49,260.83 r0 bottom
R123 "RR0306P-103-D" FP-RR0306P-103-D_0201-IPC_C 622.73,1325.33 r180 top
R124 "CRCW020120R0FNED" 0201_033 658.74,1329.77 r180 bottom
R125 "CRCW020120R0FNED" 0201_033 658.74,1294.77 r180 bottom
R126 "CRCW020120R0FNED" 0201_033 643.74,1259.77 r180 bottom
R127 "CRCW020120R0FNED" 0201_033 643.74,1224.77 r180 bottom
R128 "CRCW020120R0FNED" 0201_033 643.74,1189.77 r180 bottom
R129 "CRCW020120R0FNED" 0201_033 643.74,1159.77 r180 bottom
R130 "CRCW020120R0FNED" 0201_033 643.74,1124.77 r180 bottom
R131 "CRCW02010000Z0ED" 0201_Silk 260,1198.84 r0 top locked
R132 "CRCW020120R0FNED" 0201_033 643.74,1089.77 r180 bottom
R133 "CRCW02010000Z0ED" 0201_Silk 260,1163.84 r0 top locked
R134 "CRCW02010000Z0ED" 0201_Silk 260,1113.02 r0 top locked
R135 "CRCW02010000Z0ED" 0201_Silk 260,1078.02 r0 top locked
R136 "CRCW02010000Z0ED" 0201_Silk 260,1004.77 r0 top locked
R137 "CRCW02010000Z0ED" 0201_Silk 260,969.77 r0 top locked
R138 "RR0306P-103-D" FP-RR0306P-103-D_0201-IPC_C 622.73,1373.63 r180 top
R139 "CRCW040210K0FKED" 0402L 960,1724.77 r90 bottom
R140 "CRCW02010000Z0ED" 0201_Silk 658.74,1364.77 r180 bottom
R141 "RC0201JR-07510RL" 0201L 302.97,1414.19 r270 top
R142 "CRCW040210K0FKED" 0402L 965,1644.77 r0 bottom
R143 "CRCW02010000Z0ED" 0201 888.74,1724.77 r90 bottom
R144 "CRCW02010000Z0ED" 0201 833.74,1724.77 r90 bottom
R145 "CRCW040210K0FKED" 0402L 798.74,1724.77 r270 bottom
R146 "CRCW040210K0FKED" 0402L 925,1724.77 r270 bottom
R147 "CRCW040210K0FKED" 0402L 965,1609.77 r180 bottom
R148 "CRCW020120R0FNED" 0201_033 1196.94,469.21 r270 bottom
R149 "CRCW020120R0FNED" 0201_033 1234.31,469.21 r270 bottom
R150 "CRCW040210K0JNED" 0402 1900,1427.68 r180 top
R151 "CRCW04020000Z0ED" 0402 977.93,1004.22 r270 bottom
R152 "CRCW040210K0FKED" 0402L 1795.94,930.89 r90 top
R153 "CRCW0402100KFKED" 0402L 1840,1609.77 r0 bottom
R154 "CRCW0402100KFKED" 0402L 1840,1574.77 r0 bottom
R155 "CRCW0402100KFKED" 0402L 1717,952.94 r90 top
R156 "CRCW0402100KFKED" 0402L 1230,1284.77 r90 bottom
R157 "CRCW040210K0FKED" 0402L 475,2360.77 r180 bottom
R158 "CRCW040210K0FKED" 0402L 475,2394.77 r0 bottom
R159 "CRCW02010000Z0ED" 0201 429.59,2292.44 r180 bottom
R160 "CRCW02010000Z0ED" 0201 429.59,2254.9 r180 bottom
R161 "CRCW040210K0FKED" 0402L 870,2324.77 r0 bottom
R162 "CRCW040210K0FKED" 0402L 870,2289.77 r180 bottom
R163 "CRCW020120R0FNED" 0201_033 1271.67,469.21 r270 bottom
R164 "CRCW020120R0FNED" 0201_033 1311.95,463.22 r270 bottom
R165 "RR0306P-103-D" FP-RR0306P-103-D_0201-IPC_C 537.82,1296.93 r270 top
R166 "CRCW020120R0FNED" 0201_033 1352.68,463.22 r270 bottom
R167 "CRCW020120R0FNED" 0201_033 1390.77,452.37 r270 bottom
R168 "CRCW020120R0FNED" 0201_033 1429.92,452.37 r270 bottom
R169 "CRCW040210K0JNED" 0402 1900,1499.77 r180 top
R170 "CRCW020120R0FNED" 0201_033 1467.83,452.37 r270 bottom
